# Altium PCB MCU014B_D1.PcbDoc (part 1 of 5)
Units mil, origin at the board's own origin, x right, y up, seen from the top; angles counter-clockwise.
Board outline 2300.04 x 4058 mil, 4 copper layers (TOP, GND, PWR, BOTTOM), stack 48.84 mil thick; 371 components, 238 nets, 1148 pads, 688 vias.
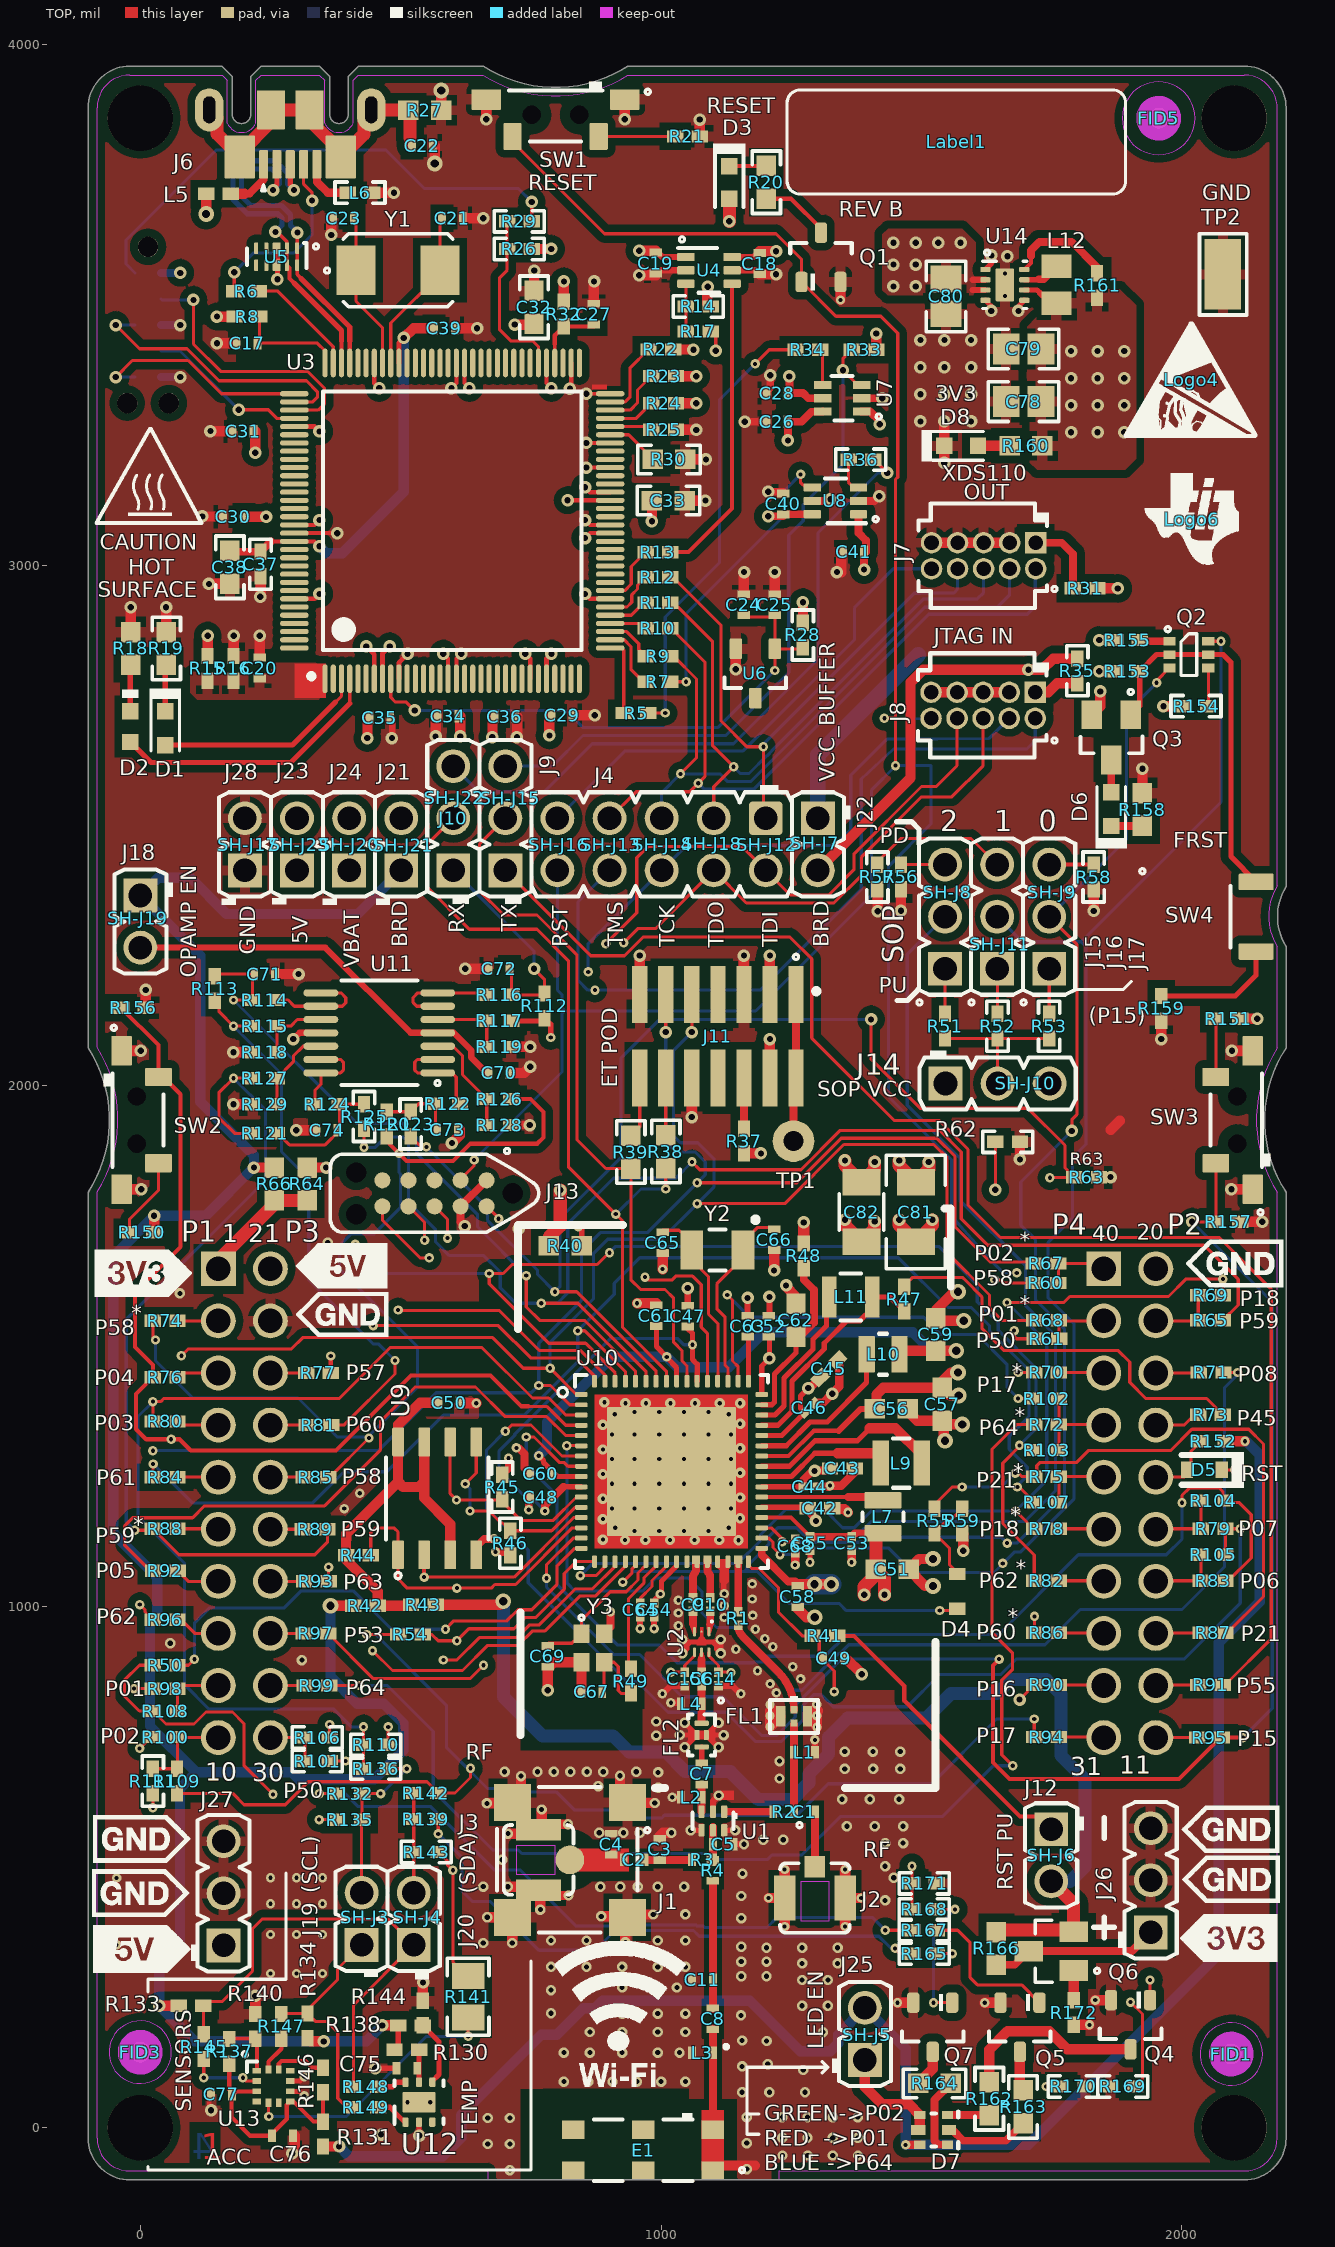
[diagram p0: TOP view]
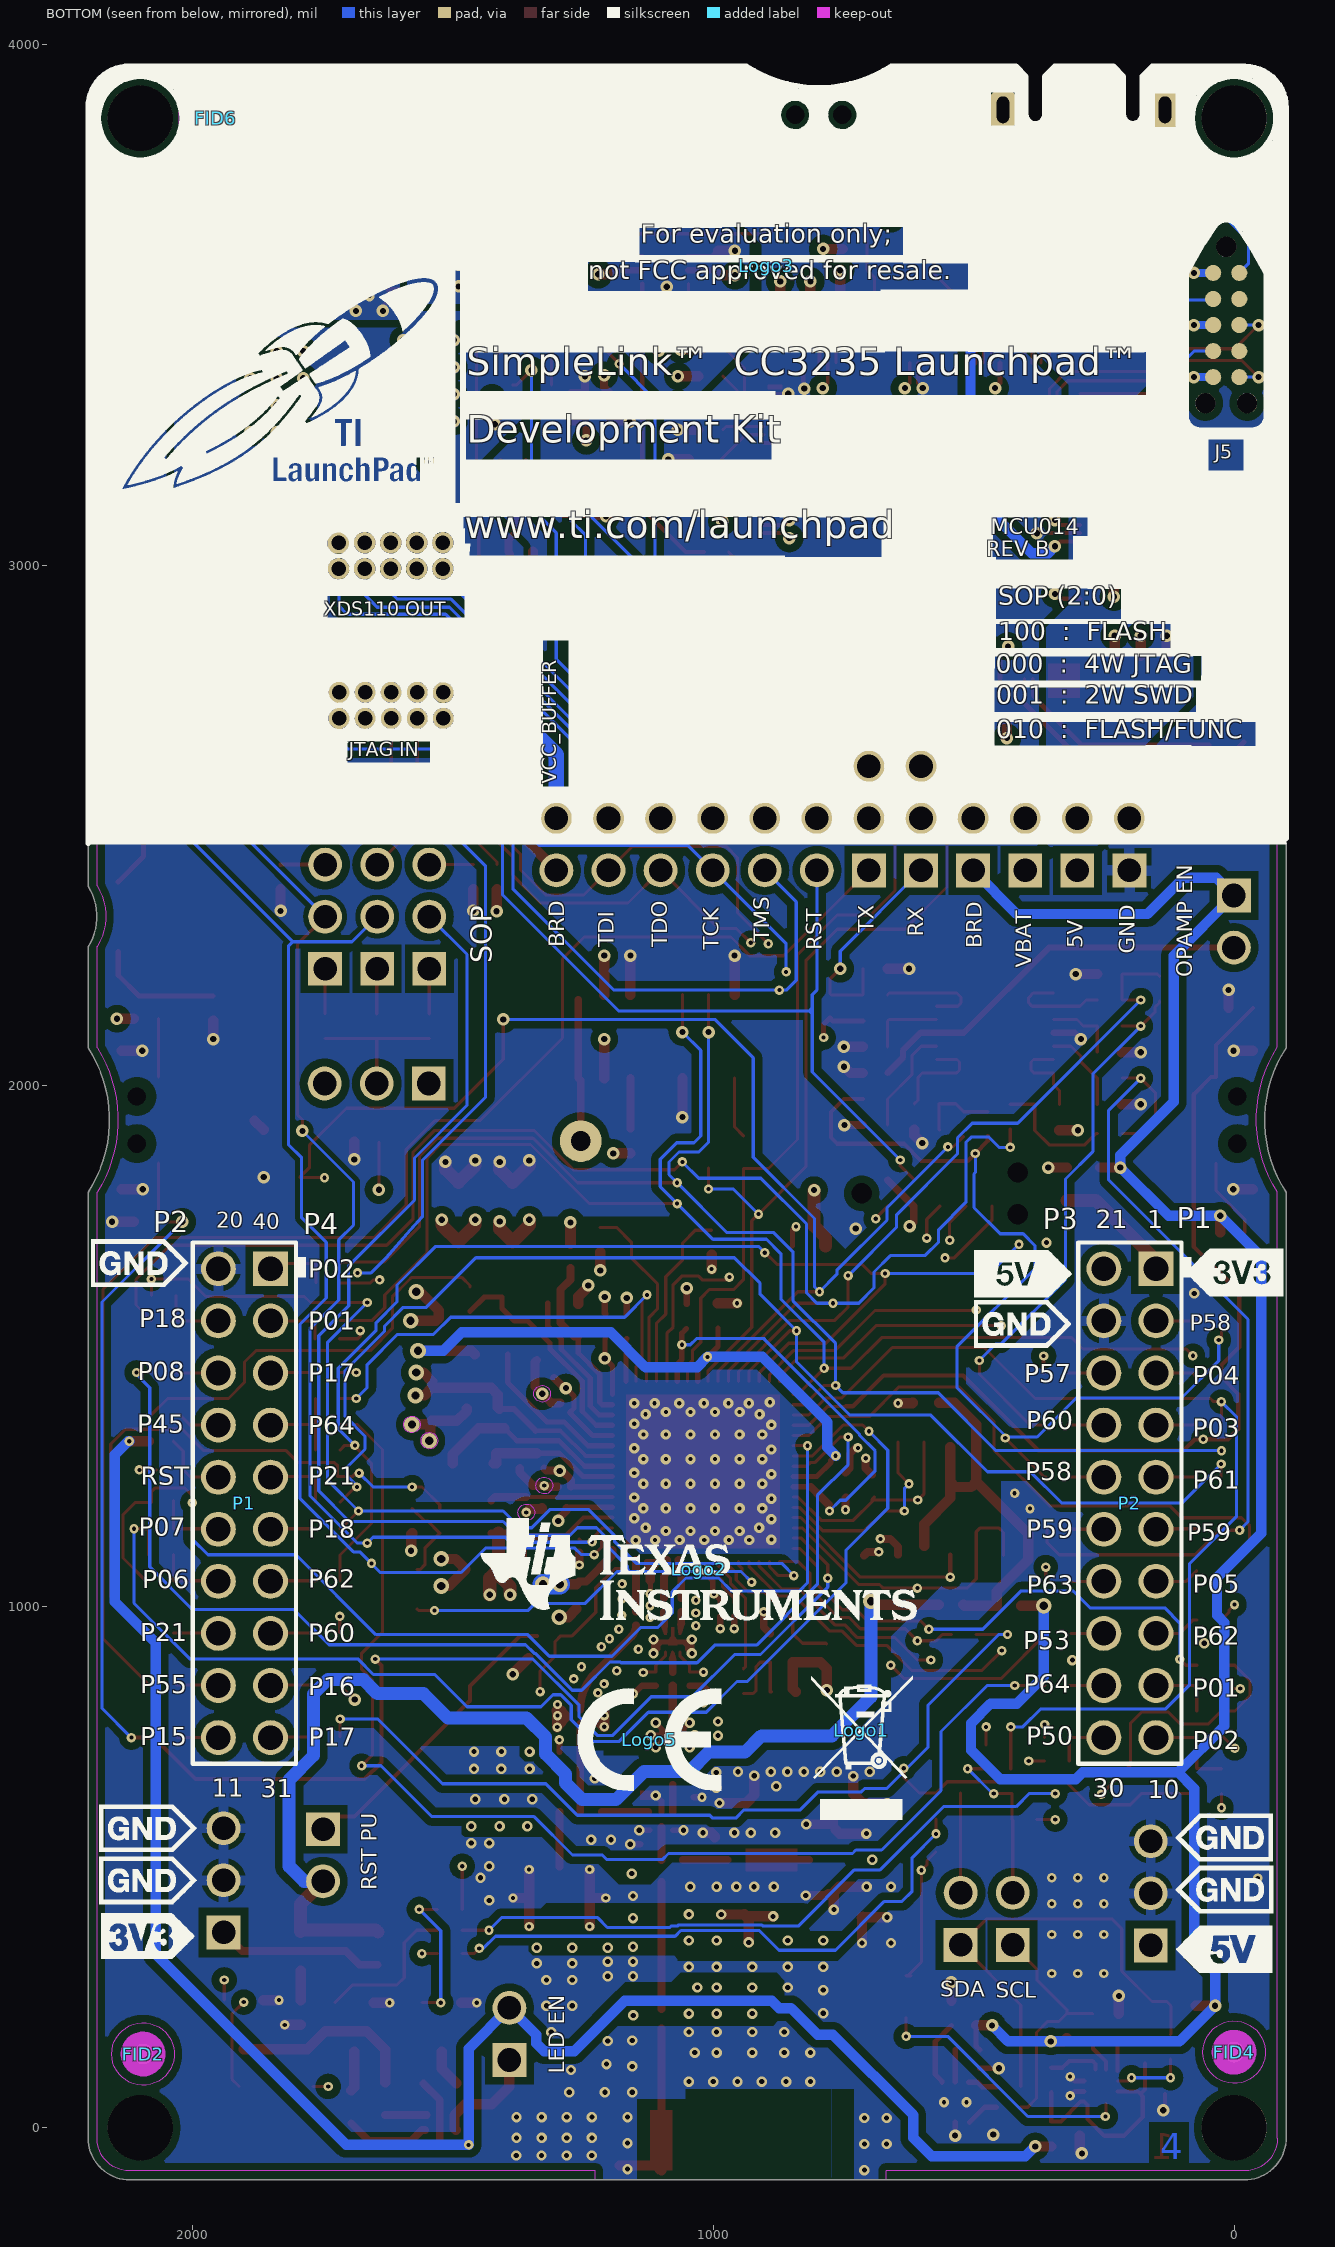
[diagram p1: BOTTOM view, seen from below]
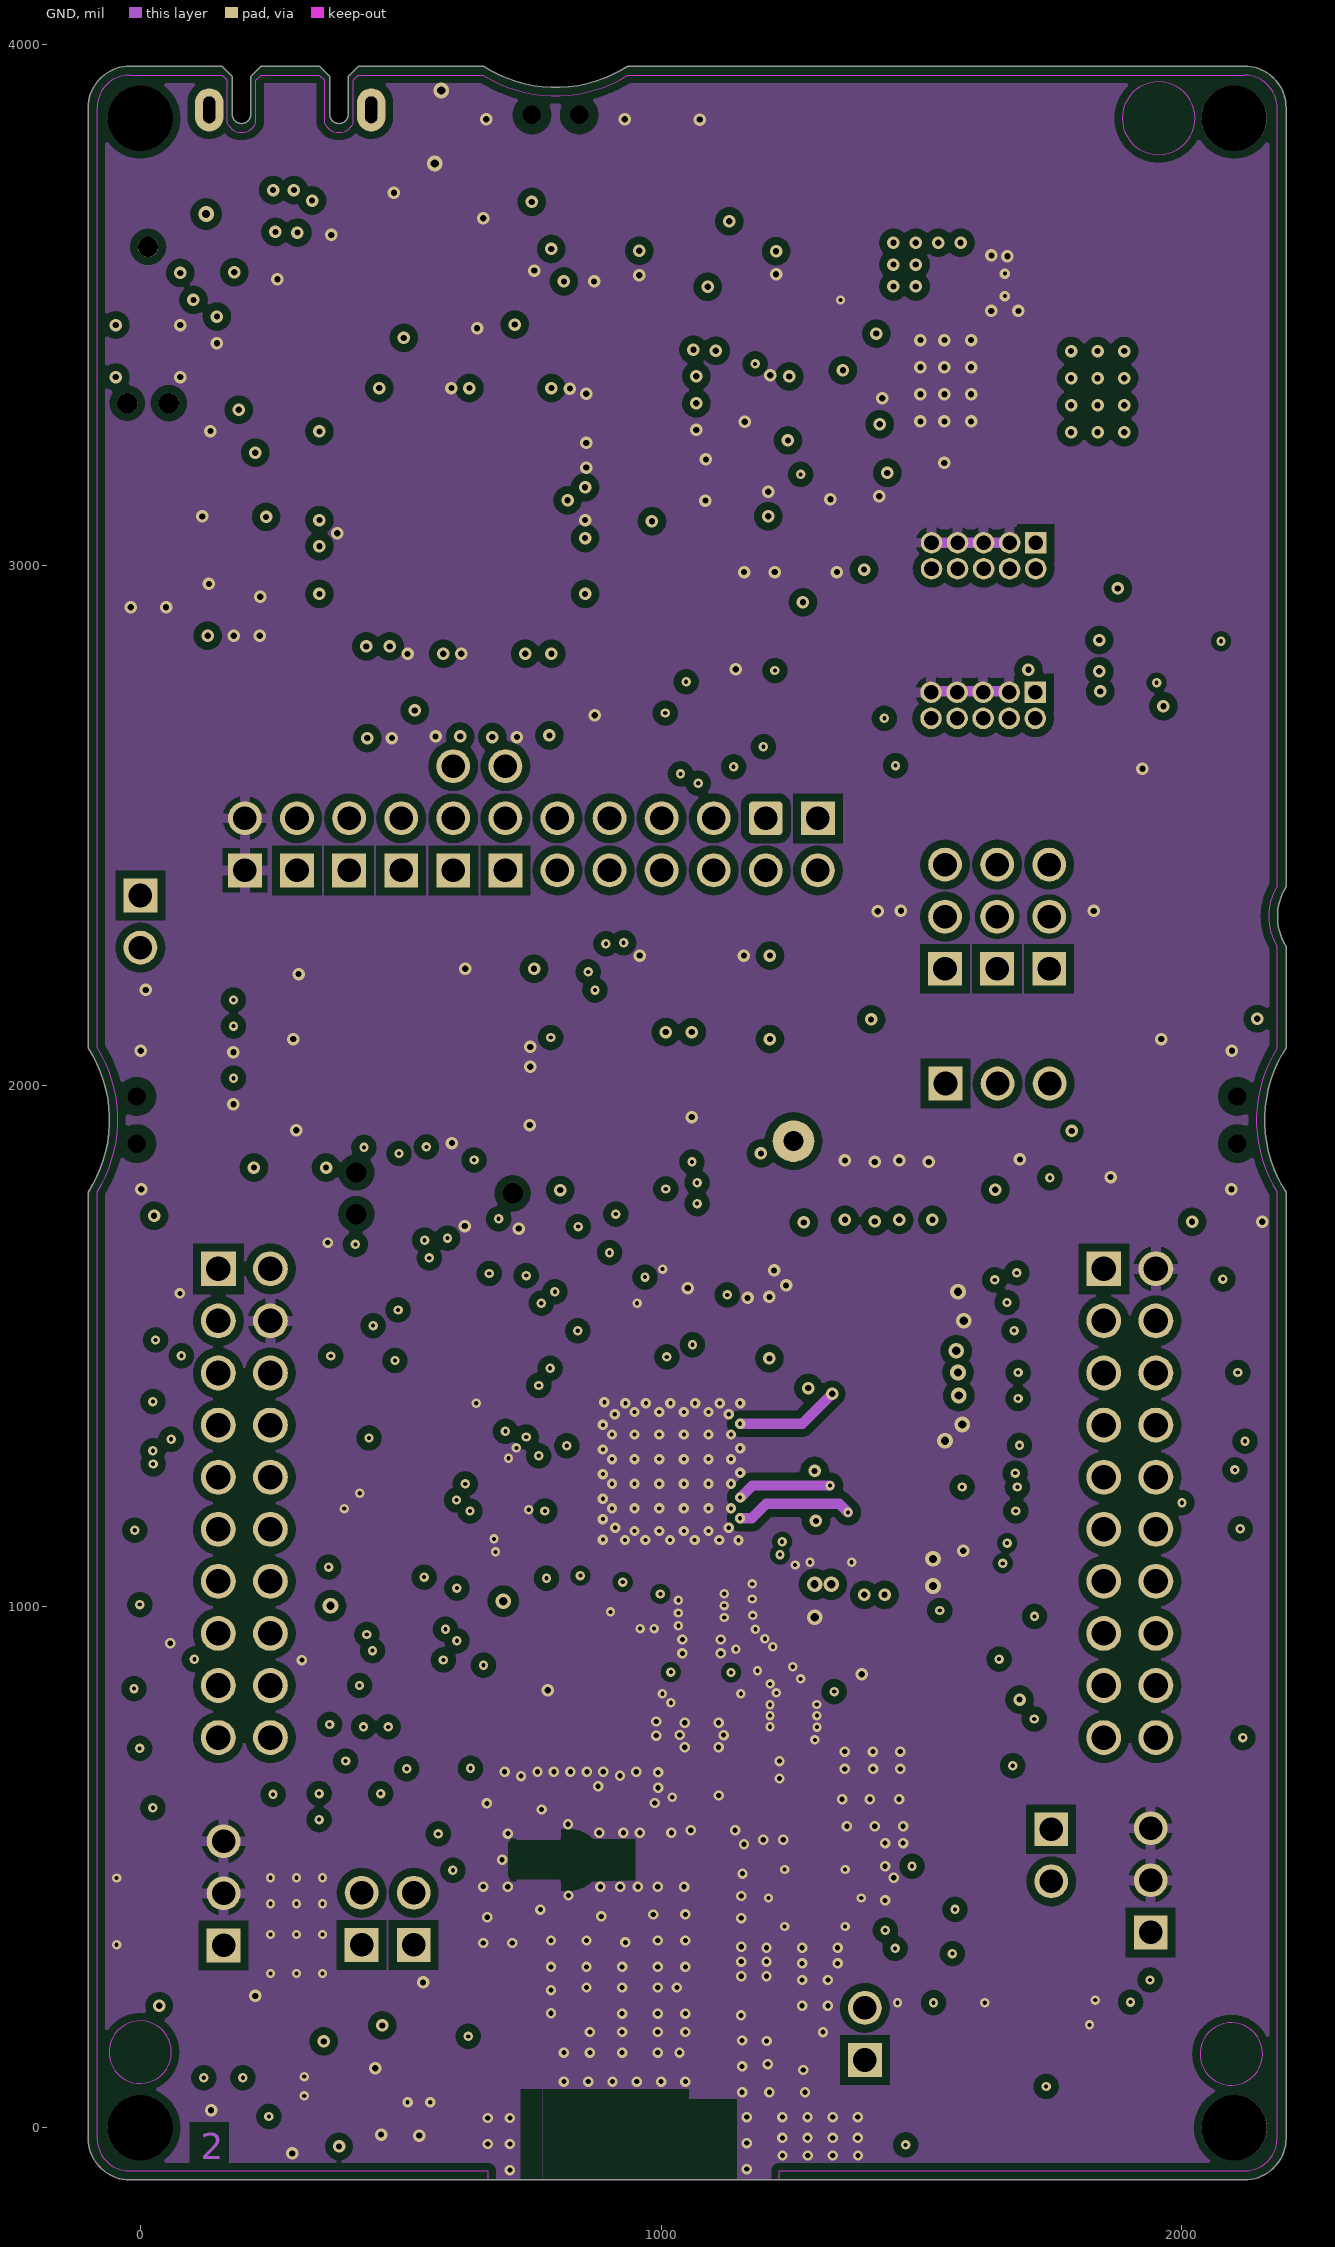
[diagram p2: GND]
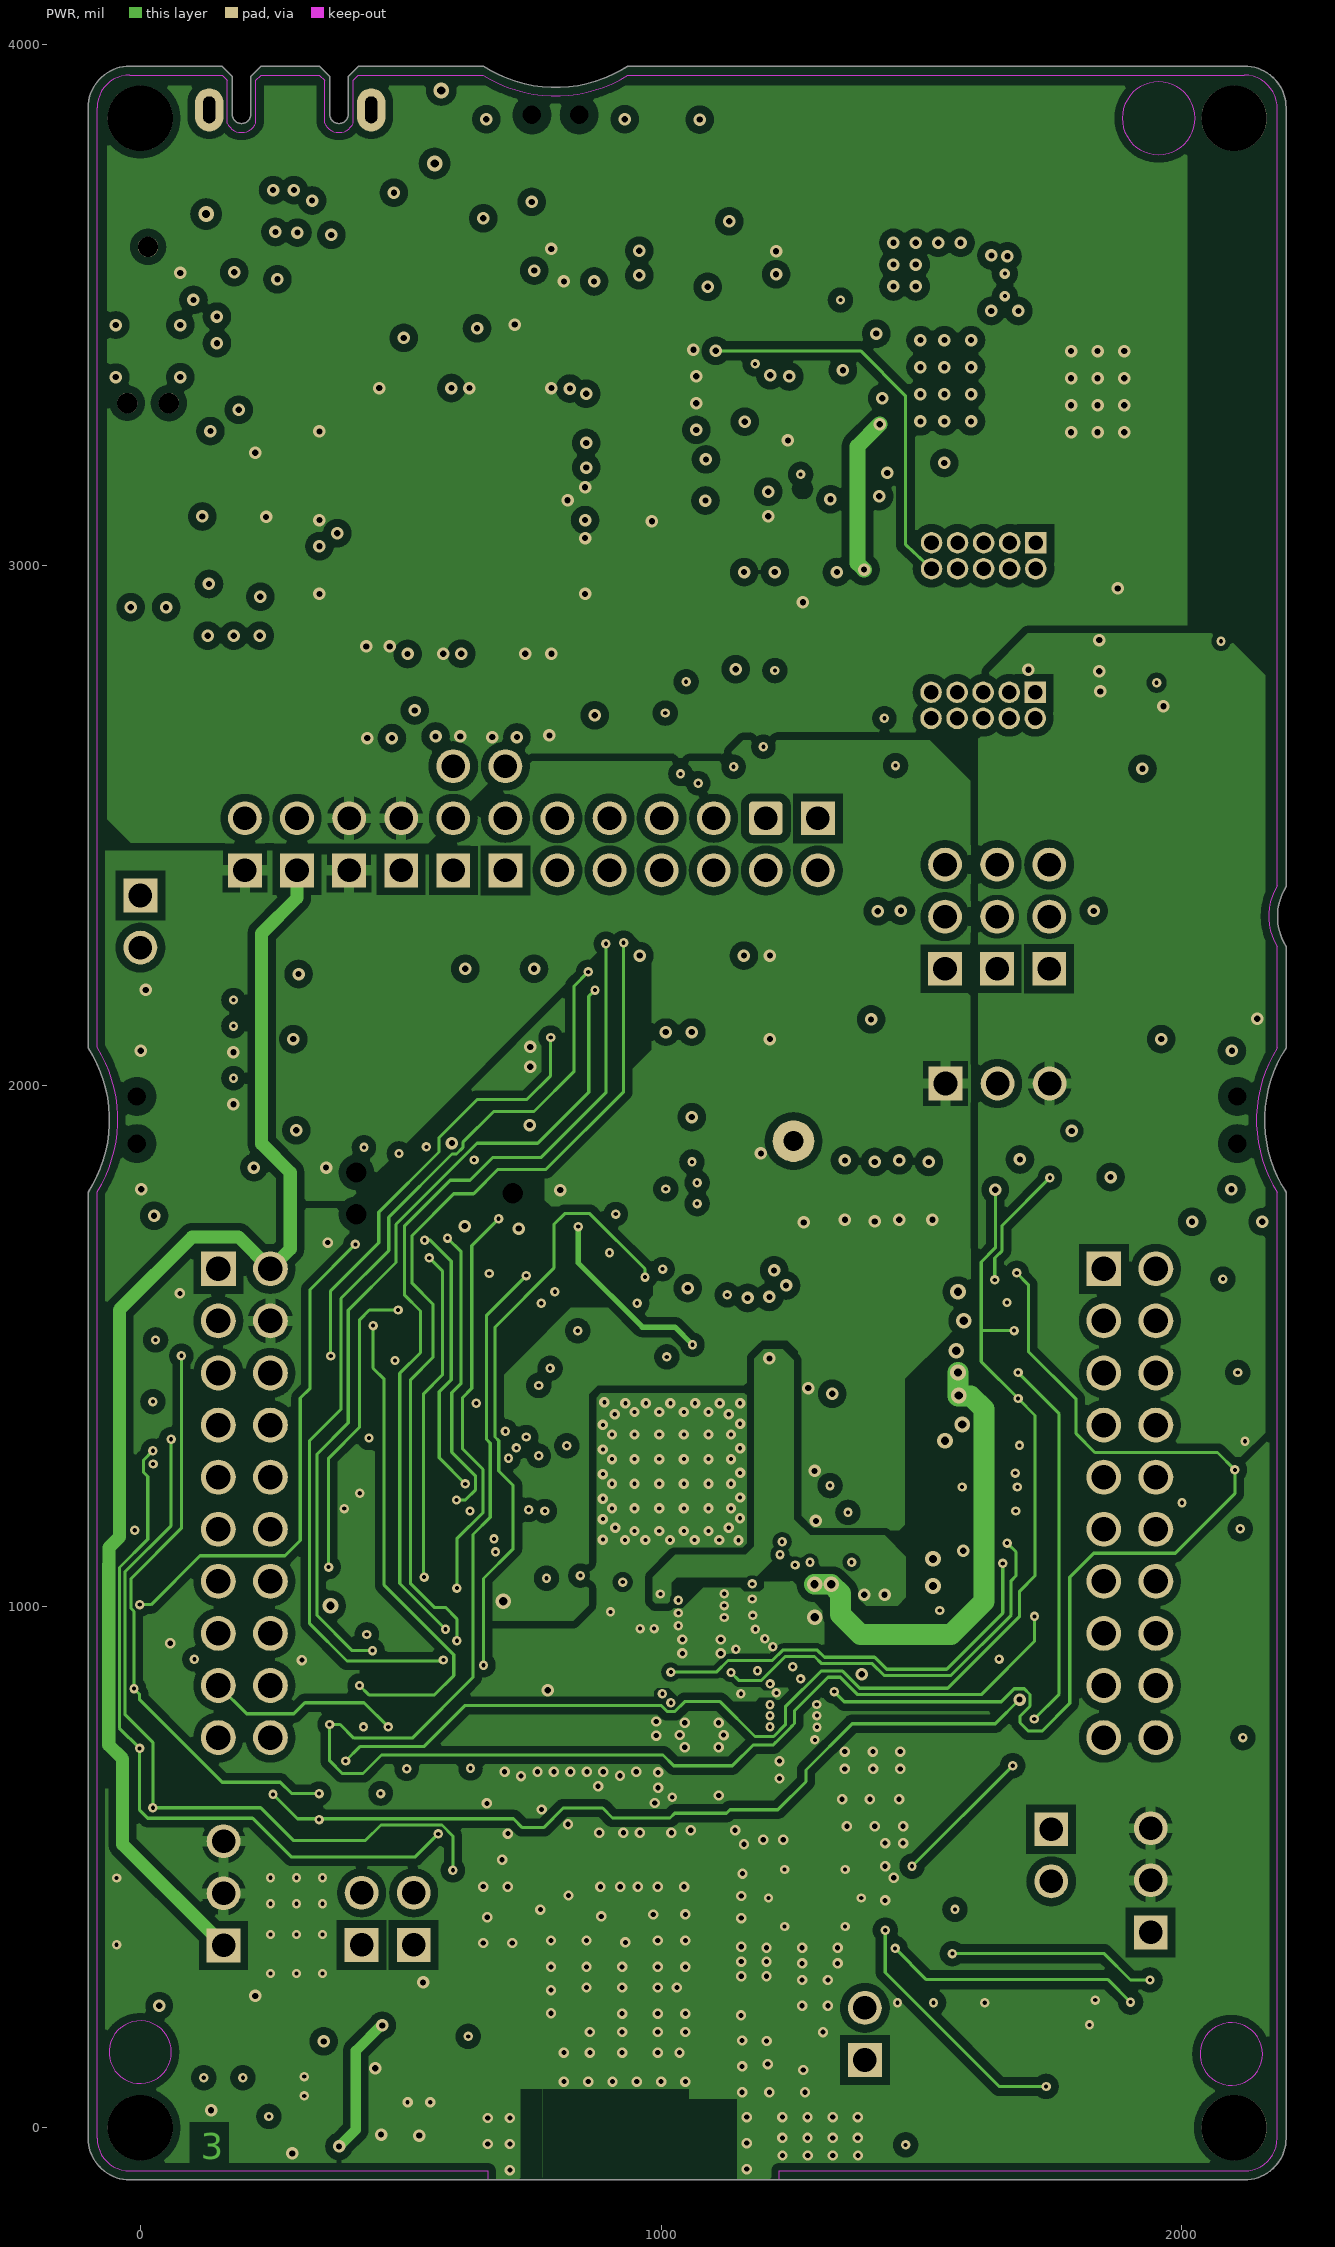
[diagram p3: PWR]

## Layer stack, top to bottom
Top Solder: solder mask 0.8, Solder Resist, Dk 4.1
TOP: signal copper 1.69
Dielectric1: core 9.3, FR-4 High Tg, Dk 3.9
GND: signal copper 1.42
Dielectric2: prepreg 24.02, FR-4 High Tg, Dk 4.24
PWR: signal copper 1.42
Dielectric3: core 9.3, FR-4 High Tg, Dk 3.9
BOTTOM: signal copper 1.69
Bottom Solder: solder mask 0.8, Solder Resist, Dk 4.1

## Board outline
-100,-20 -100,1796 ccw(c-313.24,1934.59) -100,2073.19 -100,3878 cw(c-20,3878) -20,3958 157.09,3958 176.78,3938.31 176.78,3865.48 ccw(c194.5,3865.48) 212.21,3865.48 212.21,3938.31 231.9,3958 344.1,3958 363.79,3938.31 363.79,3865.48 ccw(c381.5,3865.48) 399.22,3865.48 399.22,3938.31 418.91,3958 658.79,3958 ccw(c797.38,4171.24) 935.97,3958 2120,3958 cw(c2120,3878) 2200,3878 2200.01,2382.86 ccw(c2291.39,2325.29) 2200.04,2267.68 2200,2073.19 ccw(c2413.24,1934.59) 2200,1796 2200,-20 cw(c2120,-20) 2120,-100 -20,-100 cw(c-20,-20)

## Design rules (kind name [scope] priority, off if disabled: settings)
AssemblyTestPointUsage [All] p1 off:
Clearance Clearance_CPWG [InNetClass('RF_CPWG') vs inpoly] p1: gap=10 ignorepadtopadclearanceinfootprint=FALSE
Clearance Clearance_witinRoom1 [WithinRoom('Room1') and isvia vs InPoly] p2: gap=6 ignorepadtopadclearanceinfootprint=FALSE except(0: Arc-Hole Track-Hole SMDPad-Hole THPad-Hole Via-Hole Fill-Hole Poly-Hole Region-Hole Text-Hole)
Clearance Clearance_Via [WithinRoom('RoomVia') and IsVia vs InPoly and InNet('GND')] p3: gap=10 ignorepadtopadclearanceinfootprint=FALSE except(0: Arc-Hole Track-Hole SMDPad-Hole THPad-Hole Via-Hole Fill-Hole Poly-Hole Region-Hole Text-Hole)
Clearance Clearance_SMAPad [Inpoly vs ispad and InComponent('J1')] p4: gap=31.39 ignorepadtopadclearanceinfootprint=FALSE except(0: Arc-Hole Track-Hole SMDPad-Hole THPad-Hole Via-Hole Fill-Hole Poly-Hole Region-Hole Text-Hole)
Clearance Clearance_J1&J3 [InComponent('J1') vs InComponent('J3')] p5: gap=0 ignorepadtopadclearanceinfootprint=FALSE
Clearance Clearance_U3 [InComponent('U3') vs InComponent('U3')] p6: gap=4.8 ignorepadtopadclearanceinfootprint=FALSE except(0: Arc-Hole Track-Hole SMDPad-Hole THPad-Hole Via-Hole Fill-Hole Poly-Hole Region-Hole Text-Hole)
Clearance Clearance_Room2 [WithinRoom('Room_2')] p7: gap=4 ignorepadtopadclearanceinfootprint=FALSE except(0: Arc-Hole Track-Hole SMDPad-Hole THPad-Hole Via-Hole Fill-Hole Poly-Hole Region-Hole Text-Hole)
Clearance Clearance_GPIO_26&27 [(InNet('P30_GPIO_27') OR InNet('P29_GPIO_26')) AND Isvia and WithinRoom('Room1') vs inpoly and (OnLayer('gnd') or OnLayer('pwr'))] p8: gap=6 ignorepadtopadclearanceinfootprint=FALSE except(0: Arc-Hole Track-Hole SMDPad-Hole THPad-Hole Via-Hole Fill-Hole Poly-Hole Region-Hole Text-Hole)
Clearance Clearance_NetC69_1 [InNet('NetC69_1') or InNet('NetC65_1') or InNet('SOP0') or InNet('SOP1') vs InPoly] p9: gap=10 ignorepadtopadclearanceinfootprint=FALSE except(0: Arc-Hole Track-Hole SMDPad-Hole THPad-Hole Via-Hole Fill-Hole Poly-Hole Region-Hole Text-Hole)
Clearance Clearance_MH [InPadClass('MH') vs InPoly] p10: gap=20 ignorepadtopadclearanceinfootprint=FALSE except(0: Arc-Hole Track-Hole SMDPad-Hole THPad-Hole Via-Hole Fill-Hole Poly-Hole Region-Hole Text-Hole)
Clearance Clearance_U14 [InComponent('U14') vs InComponent('U14')] p11: gap=4.8 ignorepadtopadclearanceinfootprint=FALSE except(0: Arc-Hole Track-Hole SMDPad-Hole THPad-Hole Via-Hole Fill-Hole Poly-Hole Region-Hole Text-Hole)
Clearance Clearance_10 [InNetClass('Impedance') vs Inpoly] p12: gap=30 ignorepadtopadclearanceinfootprint=FALSE except(0: Arc-Hole Track-Hole SMDPad-Hole THPad-Hole Via-Hole Fill-Hole Poly-Hole Region-Hole Text-Hole)
Clearance Clearance_Exposed [OnLayer('Keep-Out Layer') vs InComponentClass('Expose')] p13: gap=0 ignorepadtopadclearanceinfootprint=FALSE
Clearance Clearance_Antenna [InComponent('E1') and IsKeepOut vs InPoly] p14: gap=0 ignorepadtopadclearanceinfootprint=FALSE
Clearance Clearance_8 [InPadClass('u1') vs istrack] p15: gap=5.9 ignorepadtopadclearanceinfootprint=FALSE except(0: Arc-Hole Track-Hole SMDPad-Hole THPad-Hole Via-Hole Fill-Hole Poly-Hole Region-Hole Text-Hole)
Clearance Clearance_7 [InPadClass('u1') vs InPadClass('u1')] p16: gap=5.9 ignorepadtopadclearanceinfootprint=FALSE except(0: Arc-Hole Track-Hole SMDPad-Hole THPad-Hole Via-Hole Fill-Hole Poly-Hole Region-Hole Text-Hole)
Clearance Clearance_6 [InNet('NetC49_2') vs InPolygon] p17: gap=15 ignorepadtopadclearanceinfootprint=FALSE except(0: Arc-Hole Track-Hole SMDPad-Hole THPad-Hole Via-Hole Fill-Hole Poly-Hole Region-Hole Text-Hole)
Clearance Clearance_5 [InNet('NetC49_1') vs InPolygon] p18: gap=15 ignorepadtopadclearanceinfootprint=FALSE except(0: Arc-Hole Track-Hole SMDPad-Hole THPad-Hole Via-Hole Fill-Hole Poly-Hole Region-Hole Text-Hole)
Clearance Clearance_4 [InNet('NetFL1_3') vs InPolygon] p19: gap=15 ignorepadtopadclearanceinfootprint=FALSE except(0: Arc-Hole Track-Hole SMDPad-Hole THPad-Hole Via-Hole Fill-Hole Poly-Hole Region-Hole Text-Hole)
Clearance Clearance_3 [InNet('NetFL1_1') vs InPolygon] p20: gap=15 ignorepadtopadclearanceinfootprint=FALSE except(0: Arc-Hole Track-Hole SMDPad-Hole THPad-Hole Via-Hole Fill-Hole Poly-Hole Region-Hole Text-Hole)
Clearance Clearance_2 [InNet('NetJ24_2') vs InPolygon] p21: gap=15 ignorepadtopadclearanceinfootprint=FALSE except(0: Arc-Hole Track-Hole SMDPad-Hole THPad-Hole Via-Hole Fill-Hole Poly-Hole Region-Hole Text-Hole)
Clearance Clearance_PAD [IsPad vs IsVia] p22: gap=8 ignorepadtopadclearanceinfootprint=FALSE except(0: Arc-Hole Track-Hole SMDPad-Hole THPad-Hole Via-Hole Fill-Hole Poly-Hole Region-Hole Text-Hole)
Clearance Clearance_net1 [InNet('NetJ24_1') vs InPolygon] p23: gap=15 ignorepadtopadclearanceinfootprint=FALSE except(0: Arc-Hole Track-Hole SMDPad-Hole THPad-Hole Via-Hole Fill-Hole Poly-Hole Region-Hole Text-Hole)
Clearance Clearance_Pad_class [InPadClass('Pad To Pad') vs IsPad] p24: gap=7.7 ignorepadtopadclearanceinfootprint=FALSE except(0: Arc-Hole Track-Hole SMDPad-Hole THPad-Hole Via-Hole Fill-Hole Poly-Hole Region-Hole Text-Hole)
Clearance Clearance_Pad_class_1 [InComponent('FID1') or              InComponent('FID2') or  InComponent('FID3') or        InComponent('FID4') or              InComponent('FID5') or  InComponent('FID6') vs IsKeepOut] p25: gap=0 ignorepadtopadclearanceinfootprint=FALSE except(7.7: Arc-Arc Arc-Track Track-Track)
Clearance Clearance_Poly_Poly [InPolygon vs InPolygon] p26: gap=15 ignorepadtopadclearanceinfootprint=FALSE except(0: Arc-Hole Track-Hole SMDPad-Hole THPad-Hole Via-Hole Fill-Hole Poly-Hole Region-Hole Text-Hole)
Clearance Clearance_VDD_ANA [inpoly and innet('VDD_ANA') and OnLayer('PWR') vs IsVia] p27: gap=8 ignorepadtopadclearanceinfootprint=FALSE except(0: Arc-Hole Track-Hole SMDPad-Hole THPad-Hole Via-Hole Fill-Hole Poly-Hole Region-Hole Text-Hole)
Clearance Clearance_Poly_Others [InPolygon] p28: gap=15 ignorepadtopadclearanceinfootprint=FALSE except(0: Arc-Hole Track-Hole SMDPad-Hole THPad-Hole Via-Hole Fill-Hole Poly-Hole Region-Hole Text-Hole)
Clearance Clearance_1 [iskeepout] p29: gap=1 ignorepadtopadclearanceinfootprint=FALSE except(0: Arc-Hole Track-Hole SMDPad-Hole THPad-Hole Via-Hole Fill-Hole Poly-Hole Region-Hole Text-Hole)
Clearance Clearance_9 [InNet('XDSET_DP') vs InNet('XDSET_DM')] p30: gap=6 ignorepadtopadclearanceinfootprint=FALSE except(0: Arc-Hole Track-Hole SMDPad-Hole THPad-Hole Via-Hole Fill-Hole Poly-Hole Region-Hole Text-Hole)
Clearance [All] p31: gap=3.5 ignorepadtopadclearanceinfootprint=FALSE
ComponentClearance ComponentClearance_Shunt [HasFootprint('Wurth_60900213421')] p1: gap=0 collisioncheckmode=3 verticalgap=0 showdistances=FALSE
ComponentClearance ComponentClearance_Overlap [InComponentClass('Overlap') vs InComponentClass('Overlap')] p2: gap=0 collisioncheckmode=3 verticalgap=0 showdistances=FALSE
ComponentClearance ComponentClearance_SMA&UFL [InComponent('J1') vs InComponent('J3')] p3: gap=0 collisioncheckmode=3 verticalgap=0 showdistances=FALSE
ComponentClearance ComponentClearance_C7_R168 [InComponent('C7') vs InComponent('R168')] p4: gap=0 collisioncheckmode=3 verticalgap=0 showdistances=FALSE
ComponentClearance ComponentClearance_R3_R170 [InComponent('R3') vs InComponent('R4')] p5: gap=0 collisioncheckmode=3 verticalgap=0 showdistances=FALSE
ComponentClearance [All] p6: gap=3.5 collisioncheckmode=3 verticalgap=3.5 showdistances=FALSE
DiffPairsRouting [All] p1: maxlimit=10 minlimit=6 mostfreqgap=6 toplayer_minwidth=8 toplayer_maxwidth=15 toplayer_prefwidth=10 midlayer1_minwidth=8 midlayer1_maxwidth=15 midlayer1_prefwidth=10 midlayer2_minwidth=8 midlayer2_maxwidth=15 midlayer2_prefwidth=10 bottomlayer_minwidth=8 bottomlayer_maxwidth=15 bottomlayer_prefwidth=10 maxuncoupledlength=500
FabricationTestPointUsage [All] p1 off: valid=0 allowmultiple=FALSE
FabricationTestpoint [All] p1 off: side=3 testpointundercomponent=TRUE minsize=40 maxsize=100 preferedsize=60 minholesize=0 maxholesize=40 preferedholesize=32 testpointgrid=1 allowsidetop=TRUE allowsidebottom=TRUE usegrid=TRUE gridtolerance=0.01
Height [All] p1: minheight=0 maxheight=1300 prefheight=500
HoleSize [All] p1: absolutevalues=TRUE maxlimit=125 minlimit=5.9 maxpercent=80.000 minpercent=20.000
MinimumAnnularRing [All] p1: minimumring=4
MinimumSolderMaskSliver [All] p1: minsoldermaskwidth=3
PlaneClearance [All] p1: clearance=8
PlaneConnect PlaneConnect_1 [All] p1: planeconnectstyle=Direct reliefexpansion=20 reliefentries=4 reliefconductorwidth=10 reliefairgap=10
PolygonConnect PolygonConnect_1 [isvia] p1: connectstyle=Direct reliefconductorwidth=10 reliefentries=4 polygonreliefangle="90 Angle" airgapwidth=10
PolygonConnect [InComponentClass('CC3200Gen3_AntennaRFSection') or InPadClass('direct connect')] p2: connectstyle=Direct reliefconductorwidth=10 reliefentries=4 polygonreliefangle="90 Angle" airgapwidth=10
PolygonConnect PolygonConnect_SMD [All] p3: connectstyle=Relief reliefconductorwidth=20 reliefentries=4 polygonreliefangle="90 Angle" airgapwidth=10
RoomDefinition RoomVia [InComponentClass('Components Class 1')] p1: confinementstyle=ConfineIn formatcopy=TRUE lockcomponents=FALSE outline 834.49,1100.65 1180.32,1100.65 1180.32,856.05 834.49,856.05
RoutingVias [All] p1: holewidth=8 width=18 viastyle="Through Hole" minholewidth=7.8 minwidth=12 maxholewidth=28 maxwidth=50
ShortCircuit ShortCircuit_1 [InPadClass('FID')] p1: allowed=TRUE
ShortCircuit [All] p2: allowed=FALSE
SilkToSilkClearance SilkToSilkClearance_Fill [IsObjectKind('Fill')] p1: silktosilkclearance=0
SilkToSilkClearance SilkToSilkClearance_pb-logo [(HasFootprint('Pb-Free_Overlay_Medium') OR HasFootprint('Pb-Free_Overlay_Small')) vs (HasFootprint('Pb-Free_Overlay_Medium') OR HasFootprint('Pb-Free_Overlay_Small'))] p2: silktosilkclearance=0
SilkToSilkClearance SilkToSilkClearance_invert [IsObjectKind('Text')] p3: silktosilkclearance=0
SilkToSilkClearance [All] p4: silktosilkclearance=3
SilkToSolderMaskClearance SilkToSolderMaskClearance_4 [InComponent('P2')] p1: minsilkscreentomaskgap=0 clearancetoexposedcopper=TRUE
SilkToSolderMaskClearance SilkToSolderMaskClearance_3 [OnLayer('Bottom Silkscreen')] p2: minsilkscreentomaskgap=0 clearancetoexposedcopper=TRUE
SilkToSolderMaskClearance SilkToSolderMaskClearance_1 [InComponent('J1') or InComponent('J3')] p3: minsilkscreentomaskgap=1 clearancetoexposedcopper=TRUE
SilkToSolderMaskClearance SilkToSolderMaskClearance_2 [InComponent('J7') or InComponent('J11') or  InComponent('J9') or InComponent('J8') or  InComponent('J24') or InComponent('J26') or InComponent('J25') or InComponent('J23') or InComponent('FID5') or InComponent('FID6')  or InComponent('J6') or InComponent('J4') or  InComponent('J29')] p4: minsilkscreentomaskgap=0 clearancetoexposedcopper=TRUE
SilkToSolderMaskClearance [IsPad] p5: minsilkscreentomaskgap=3 clearancetoexposedcopper=FALSE
SilkToSolderMaskClearance SilkscreenOverComponentPads [IsPad] p6: minsilkscreentomaskgap=3 clearancetoexposedcopper=TRUE
SolderMaskExpansion SolderMaskExpansion_PTH [InPadClass('PTH')] p1: expansion=2.5
SolderMaskExpansion SolderMaskExpansion_MH [InPadClass('MH')] p2: expansion=5
SolderMaskExpansion SolderMaskExpansion_1 [InPadClass('MAsk')] p3: expansion=0.9
SolderMaskExpansion [All] p4: expansion=0
Width [All] p1: maxlimit=100 minlimit=5 preferedwidth=10
17 further rules are at their usual default settings.

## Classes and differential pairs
component class "New Class": C47 C55 C68 L4
pad class MH: SW1- SW2- SW3- SW4-MH1 SW4-MH2
pad class MAsk: U1-1 U1-2 U1-3 U1-4 U1-5 U1-6 U1-7 U1-8 U1-9 U1-10 U1-11 U1-12 U1-13 U1-14 U1-15 U1-16 U1-17 U1-18 U1-19 U1-20 U1-21 U1-22 U1-23 U1-24 U1-25 U1-26 U1-27 U1-28 U1-29 U1-30 U1-31 U1-32 U1-33 U1-34 U1-35 U1-36 U1-37 U1-38 U1-39 U1-40 U1-41 U1-42 U1-43 U1-44 U1-45 U1-46 U1-47 U1-48 U1-49 U1-50 U1-51 U1-52 U1-53 U1-54 U1-55 U1-56 U1-57 U1-58 U1-59 U1-60 U1-61 U1-62 U1-63 U1-64 U1-65 U1-66 U1-67 U1-68 U1-69 U1-70 U1-71 U1-72 U1-73 U1-74 U1-75 U1-76 U1-77 U1-78 U1-79 U1-80 U1-81 U1-82 U1-83 U1-84 U1-85 U1-86 U1-87 U1-88 U1-89 U1-90 U1-91 U1-92 U1-93 U1-94 U1-95 U1-96 U1-97 U1-98 U1-99 U1-100 U1-101 U1-102 U1-103 U1-104 U1-105 U1-106 U1-107 U1-108 U1-109 U1-110 U1-111 U1-112 U1-113 U1-114 U1-115 U1-116 U1-117 U1-118 U1-119 U1-120 U1-121 U1-122 U1-123 U1-124 U1-125 U1-126 U1-127 U1-128
pad class "direct connect": C3-2 C4-2 C5-2 C11-2 C14-2 C15-2 FL1-2 FL1-4 L1-2 L2-2 L3-2 L4-1 U1-2 U1-4 U1-6
component class FiducialMark: FID1 FID2 FID3 FID4 FID5 FID6
component class MCU014B_D1_EngineArea: C42 C43 C44 C45 C46 C47 C48 C49 C50 C51 C52 C53 C54 C55 C56 C57 C58 C59 C60 C61 C62 C63 C64 C65 C66 C67 C68 C69 D4 J12 J13 J14 J15 J16 J17 L7 L9 L10 L11 R40 R41 R42 R43 R44 R45 R46 R47 R48 R49 R50 R51 R52 R53 R54 R55 R56 R57 R58 R59 U9 U10 Y2 Y3
component class MCU014B_D1_HostInterface_ADC: C70 C71 C72 C73 C74 J18 P1 P2 R60 R61 R62 R63 R64 R65 R66 R67 R68 R69 R70 R71 R72 R73 R74 R75 R76 R77 R78 R79 R80 R81 R82 R83 R84 R85 R86 R87 R88 R89 R90 R91 R92 R93 R94 R95 R96 R97 R98 R99 R100 R101 R102 R103 R104 R105 R106 R107 R108 R109 R110 R111 R112 R113 R114 R115 R116 R117 R118 R119 R120 R121 R122 R123 R124 R125 R126 R127 R128 R129 U11
component class MCU014B_D1_EmulationCircuit: C17 C18 C19 C20 C21 C22 C23 C24 C25 C26 C27 C28 C29 C30 C31 C32 C33 C34 C35 C36 C37 C38 C39 C40 C41 D1 D2 D3 J4 J5 J6 J7 J8 J9 J10 J11 L5 L6 Q1 R5 R6 R7 R8 R9 R10 R11 R12 R13 R14 R15 R16 R17 R18 R19 R20 R21 R22 R23 R24 R25 R26 R27 R28 R29 R30 R31 R32 R33 R34 R35 R36 R37 R38 R39 SW1 TP1 U3 U4 U5 U6 U7 U8 Y1
component class MCU014B_D1_PowerLedsSwitchSensors: C75 C76 C77 C78 C79 C80 C81 C82 D5 D6 D7 D8 J19 J20 J21 J22 J23 J24 J25 J26 J27 J28 L12 Q2 Q3 Q4 Q5 Q6 Q7 R130 R131 R132 R133 R134 R135 R136 R137 R138 R139 R140 R141 R142 R143 R144 R145 R146 R147 R148 R149 R150 R151 R152 R153 R154 R155 R156 R157 R158 R159 R160 R161 R162 R163 R164 R165 R166 R167 R168 R169 R170 R171 R172 SW2 SW3 SW4 TP2 U12 U13 U14
component class AssemblyNote: ZZ1 ZZ2 ZZ3 ZZ4
component class MCU014B_D1_EVM_Hardware: FID1 FID2 FID3 FID4 FID5 FID6 Label1 Logo1 Logo2 Logo3 Logo4 Logo5 Logo6 SH-J3 SH-J4 SH-J5 SH-J6 SH-J7 SH-J8 SH-J9 SH-J10 SH-J11 SH-J12 SH-J13 SH-J14 SH-J15 SH-J16 SH-J17 SH-J18 SH-J19 SH-J20 SH-J21 SH-J22 SH-J23 ZZ1 ZZ2 ZZ3 ZZ4
component class Header: J4 J9 J10 J11 J12 J14 J15 J16 J17 J18 J19 J20 J21 J22 J23 J24 J25 J26 J27 J28
component class Label: Label1
component class Logo: Logo2 Logo6
pad class u1: U1-1 U1-2 U1-3 U1-4 U1-5 U1-6 U1-7 U1-8 U1-9 U1-10 U1-11 U1-12 U1-13 U1-14 U1-15 U1-16 U1-17 U1-18 U1-19 U1-20 U1-21 U1-22 U1-23 U1-24 U1-25 U1-26 U1-27 U1-28 U1-29 U1-30 U1-31 U1-32 U1-33 U1-34 U1-35 U1-36 U1-37 U1-38 U1-39 U1-40 U1-41 U1-42 U1-43 U1-44 U1-45 U1-46 U1-47 U1-48 U1-49 U1-50 U1-51 U1-52 U1-53 U1-54 U1-55 U1-56 U1-57 U1-58 U1-59 U1-60 U1-61 U1-62 U1-63 U1-64 U1-65 U1-66 U1-67 U1-68 U1-69 U1-70 U1-71 U1-72 U1-73 U1-74 U1-75 U1-76 U1-77 U1-78 U1-79 U1-80 U1-81 U1-82 U1-83 U1-84 U1-85 U1-86 U1-87 U1-88 U1-89 U1-90 U1-91 U1-92 U1-93 U1-94 U1-95 U1-96 U1-97 U1-98 U1-99 U1-100 U1-101 U1-102 U1-103 U1-104 U1-105 U1-106 U1-107 U1-108 U1-109 U1-110 U1-111 U1-112 U1-113 U1-114 U1-115 U1-116 U1-117 U1-118 U1-119 U1-120 U1-121 U1-122 U1-123 U1-124 U1-125 U1-126 U1-127 U1-128
component class MCU014B_D1_AntennaRFSection: C1 C2 C3 C4 C5 C6 C7 C8 C9 C10 C11 C14 C15 E1 FL1 FL2 J1 J2 J3 L1 L2 L3 L4 R1 R2 R3 R4 U1 U2
pad class PTH: J4-1 J4-2 J4-3 J4-4 J4-5 J4-6 J4-7 J4-8 J4-9 J4-10 J6-7 J6-10 J7-1 J7-2 J7-3 J7-4 J7-5 J7-6 J7-7 J7-8 J7-9 J7-10 J8-1 J8-2 J8-3 J8-4 J8-5 J8-6 J8-7 J8-8 J8-9 J8-10 J9-1 J9-2 J9-3 J10-1 J10-2 J10-3 J12-1 J12-2 J14-1 J14-2 J14-3 J15-1 J15-2 J15-3 J16-1 J16-2 J16-3 J17-1 J17-2 J17-3 J18-1 J18-2 J19-1 J19-2 J20-1 J20-2 J21-1 J21-2 J22-1 J22-2 J23-1 J23-2 J24-1 J24-2 J25-1 J25-2 J26-1 J26-2 J26-3 J27-1 J27-2 J27-3 J28-1 J28-2 P1-1 P1-2 P1-3 P1-4 P1-5 P1-6 P1-7 P1-8 P1-9 P1-10 P1-11 P1-12 P1-13 P1-14 P1-15 P1-16 P1-17 P1-18 P1-19 P1-20 P2-1 P2-2 P2-3 P2-4 P2-5 P2-6 P2-7 P2-8 P2-9 P2-10 P2-11 P2-12 P2-13 P2-14 P2-15 P2-16 P2-17 P2-18 P2-19 P2-20 TP1-1
component class Overlap: C1 C2 C5 J4 J9 J10 J15 J16 J17 J19 J20 J21 J22 J23 J24 J28 R2 R4 R138 R144
net class RF_CPWG: A_RX A_TX NetC1_1 NetC1_2 NetC2_1 NetC2_2 NetC5_1 NetC6_2 NetC7_2 NetC8_1 NetC9_1 NetC10_1 NetFL1_1 NetR2_1 RF_BG

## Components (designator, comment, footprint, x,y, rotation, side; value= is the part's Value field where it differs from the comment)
C1 "CMP-0006408-2" 0402S 1275.31,606.65 r0 top locked value=10pF
C2 "0402N8R2C500CT" 0402S 948.26,514.21 r180 top value=8.2pF
C3 "GJM1555C1HR50BB01J" 0402S 997,534.21 r90 top value=0.5pF
C4 "GJM1555C1HR50BB01J" 0402S 904.51,544.46 r90 top value=0.5pF
C5 "GJM1555C1HR50BB01J" 0402S 1119.46,544.06 r0 top value=0.5pF
C6 "GRM0335C1H1R6BA01D" 0201_033 1077.81,861.71 r90 top value=1.6pF
C7 "GJM1555C1H1R9WB01D" 0402S 1077.81,679.21 r270 top value=1.9pF
C8 "GJM1555C1H2R2BB01D" 0402S 1099.46,209.21 r270 top locked value=2.2pF
C9 "GRM0335C1H4R7BA01D" 0201_033 1061.3,1004.21 r90 top value=4.7pF
C10 "GRM0335C1H4R7BA01D" 0201_033 1094.31,1004.21 r90 top value=4.7pF
C11 "CMP-0006426-2" 0402S 1079.46,284.21 r180 top value=1pF
C14 "CC0201JRNPO8BN101" 0201 1110.31,861.71 r270 top value=100pF
C15 "CC0201JRNPO8BN101" 0201 1045.31,861.71 r270 top value=100pF
C17 "CL05B104KO5NNNC" 0402S 205.21,3426.21 r180 top locked value=0.1uF
C18 "CL05B104KO5NNNC" 0402S 1189,3579 r270 top locked value=0.1uF
C19 "CL05B104KO5NNNC" 0402S 990,3580 r270 top locked value=0.1uF
C20 "0402B103K500CT" 0402S 229.38,2802.38 r90 top locked value=0.01uF
C21 "CL05C220JB5NNNC" 0402S 599.33,3665.91 r180 top locked value=22pF
C22 "0402B103K500CT" 0402S 541.5,3805 r0 top locked value=0.01uF
C23 "CL05C220JB5NNNC" 0402S 390.58,3665.83 r0 top locked value=22pF
C24 "0402B103K500CT" 0402S 1159,2924 r90 top locked value=0.01uF
C25 "CL05A105KA5NQNC" 0402S 1218,2924 r90 top locked value=1uF
C26 "CL05B104KO5NNNC" 0402S 1222.6,3275.41 r180 top locked value=0.1uF
C27 "CL05A105KA5NQNC" 0402S 871,3482 r90 top locked value=1uF
C28 "CL05B104KO5NNNC" 0402S 1222.6,3330.41 r180 top locked value=0.1uF
C29 "0402B103K500CT" 0402S 810,2712 r0 top locked value=0.01uF
C30 "0402B103K500CT" 0402S 179,3093 r180 top locked value=0.01uF
C31 "0402B103K500CT" 0402S 197.38,3257 r180 top locked value=0.01uF
C32 "CMP-0006758-5" 0603 756,3495 r90 top locked value=0.1uF
C33 "CMP-0006758-5" 0603 1014,3124 r0 top locked value=0.1uF
C34 "CL05A105KA5NQNC" 0402S 591,2710 r180 top locked value=1uF
C35 "0402B103K500CT" 0402S 460,2707 r0 top locked value=0.01uF
C36 "CL05A105KA5NQNC" 0402S 700,2709 r0 top locked value=1uF
C37 "CMP-0006275-2" 0402 231,3002 r270 top locked value=2.2uF
C38 "CMP-0006758-5" 0603 172,2996 r270 top locked value=0.1uF
C39 "CL05A105KA5NQNC" 0402S 584,3455 r0 top locked value=1uF
C40 "CL05B104KO5NNNC" 0402S 1234.6,3117.41 r90 top locked value=0.1uF
C41 "CL05B104KO5NNNC" 0402S 1369.6,3025.41 r180 top locked value=0.1uF
C42 "CMP-0064972-2" 0402 1305,1189.5 r0 top locked value=4.7uF
C43 "CMP-0064972-2" 0402 1347.91,1265.69 r0 top value=4.7uF
C44 "GJM0335C1ER60BB01D" 0201_033 1285.79,1230.47 r0 top value=0.6pF
C45 "CMP-0064972-2" 0402 1322.32,1456.71 r45 top value=4.7uF
C46 "GJM0335C1ER50BB01D" 0201_033 1284.87,1382.18 r45 top value=0.5pF
C47 "CL05B104KO5NNNC" 0402S 1051,1558 r90 top locked value=0.1uF
C48 "CL05B104KO5NNNC" 0402S 768.62,1210 r180 top locked value=0.1uF
C49 "0402B103K500CT" 0402S 1331.06,901.65 r0 top locked value=0.01uF
C50 "CL05B104KO5NNNC" 0402S 592.87,1392.1 r0 top locked value=0.1uF
C51 "CMP-0064953-4" 0603 1444,1072 r0 top locked value=10uF
C52 "CL05B104KO5NNNC" 0402S 1207,1539 r90 top locked value=0.1uF
C53 "GJM0335C1ER20BB01D" 0201_033 1365.68,1121.74 r270 top value=0.2pF
C54 "CL03A104KP3NNNC" 0201 986.58,994.26 r270 top value=0.1uF
C55 "GJM0335C1ER60BB01D" 0201_033 1285.88,1121.74 r270 top value=0.6pF
C56 "CMP-0064952-4" 0603 1442,1380 r0 top locked value=22uF
C57 "CMP-0064952-4" 0603 1540,1389 r270 top locked value=22uF
C58 "CL05A105MP5NNNC" 0402S 1262.64,1019.79 r270 top locked value=1uF
C59 "CMP-0064953-4" 0603 1527,1523 r90 top locked value=10uF
C60 "CL05B104KO5NNNC" 0402S 768.62,1256 r180 top locked value=0.1uF
C61 "CL05B104KO5NNNC" 0402S 991,1559 r90 top locked value=0.1uF
C62 "CMP-0064953-4" 0603 1259,1550 r90 top locked value=10uF
C63 "CL05B104KO5NNNC" 0402S 1166,1539 r90 top locked value=0.1uF
C64 "CMP-0009655-3" 0201 959.69,994.26 r270 top value=0.1uF
C65 "0402N100J500CT" 0402S 1003,1699.33 r270 top locked value=10pF
C66 "0402N100J500CT" 0402S 1217,1705 r270 top locked value=10pF
C67 "0402N6R2C500CT" 0402S 866.89,837 r180 top locked value=6.2pF
C68 "GJM0335C1ER60BB01D" 0201_033 1257.24,1116.74 r270 top value=0.6pF
C69 "0402N6R2C500CT" 0402S 782.17,905 r270 top locked value=6.2pF
C70 "0402B103K500CT" 0402S 689,2025 r0 top locked value=0.01uF
C71 "0402B103K500CT" 0402S 239,2215 r0 top locked value=0.01uF
C72 "0402B103K500CT" 0402S 689,2225 r180 top locked value=0.01uF
C73 "0402B103K500CT" 0402S 590.2,1915.96 r0 top locked value=0.01uF
C74 "0402B103K500CT" 0402S 359,1915 r180 top locked value=0.01uF
C75 "CL05B104KO5NNNC" 0402S 511.81,114.17 r180 top locked value=0.1uF
C76 "CL05B104KO5NNNC" 0402S 273,-15.38 r0 top locked value=0.1uF
C77 "CL05B104KO5NNNC" 0402S 156,64.62 r180 top locked value=0.1uF
C78 "CL21A106KPFNNNE" 0805#1 1696,3314 r180 top locked value=10uF
C79 "CL21A226KOQNNNE" 0805#1 1696,3415 r180 top locked value=22uF
C80 "CL21A106KPFNNNE" 0805#1 1547,3516 r270 top locked value=10uF
C81 "CMP-0008934-2" 1206_180M 1489,1758 r90 top locked value=100uF
C82 "CMP-0008934-2" 1206_180 1385,1758 r90 top locked value=100uF
D1 "CMP-0002871-1" SML-31_Red 48,2687 r270 top locked value=Red
D2 "CMP-0002834-1" LED_SML-LX0603GW -19,2690 r90 top locked value=Green
D3 "CMP-0002892-2" WL-SMCW_YELLOW 1131,3734.7 r270 top locked value=Yellow
D4 "CDBU00340" SOD-523F 1568.87,1029.64 r270 top value=45V
D5 "CDBU00340" SOD-523F 2043,1263 r180 top locked value=45V
D6 "CMP-0002871-1" SML-31_Red 1864.21,2531.73 r90 top value=Red
D7 "CMP-0003017-2" EAST1616_RGB 1523.34,-4.33 r90 top locked value=Rgb
D8 "CMP-0002871-1" SML-31_Red 1576,3229 r0 top locked value=Red
E1 "CMP-0001857-1" Ethertronics_M830520 965.6,-42.91 r270 top locked
FID1 "CMP-0077181-1" Fiducial10-20 2094.68,141.5 r90 top
FID2 "CMP-0077181-1" Fiducial10-20 2094.68,141.5 r90 bottom
FID3 "CMP-0077181-1" Fiducial10-20 0,145 r90 top
FID4 "CMP-0077181-1" Fiducial10-20 0,145 r90 bottom
FID5 "CMP-0077181-1" Fiducial10-20 1955.31,3858 r90 top
FID6 "CMP-0077181-1" Fiducial10-20 1955.31,3858 r90 bottom locked
FL1 "CMP-0002039-2" TDK_DEA202450BT-1294C1-H 1255.31,789.51 r0 top locked value="1.02 dB"
FL2 "CMP-0002038-2" TDK_DEA165538BT-2236B1-H 1077.81,753.87 r270 top
J1 "CMP-0055832-1" Hustsan_SMA-10V21-TGG 824.87,514.21 r0 top
J2 "U.FL-R-SMT-1(01)" CONN_UFL-R-SMT-1#1 1295.31,440.99 r270 top locked
J3 "U.FL-R-SMT-1(01)" CONN_UFL-R-SMT-1#2 764.84,514.21 r180 top locked
J4 "CMP-0054806-2" WURTH_61301021121 1001,2464 r180 top locked
J5 "CMP-0075101-1" Tag_TC2050-NL#1 15,3461 r180 bottom
J6 "CMP-0055311-1" Molex_1051640001 288,3931.21 r180 top
J7 "CMP-0075533-1" Samtec_FTSH-105-01-x-D-K 1619.19,3018.01 r270 top
J8 "CMP-0075533-1" Samtec_FTSH-105-01-x-D-K 1618.28,2730.77 r270 top
J9 "CMP-0054796-1" WURTH_61300311121 701,2514 r90 top locked
J10 "CMP-0054796-1" WURTH_61300311121 601,2514 r90 top locked
J11 "CMP-0055564-1" Samtec_FTSH-107-01-x-DV 1109,2095.32 r270 top locked
J12 "CMP-0054794-1" WURTH_61300211121 1749,523 r270 top locked
J13 "TC2050-IDC-NL-FP" Tag_TC2050-NL#2 565,1794 r270 top locked
J14 "CMP-0054796-1" WURTH_61300311121 1646.01,2004.79 r0 top locked
J15 "CMP-0054796-1" WURTH_61300311121 1545.12,2325.12 r90 top locked
J16 "CMP-0054796-1" WURTH_61300311121 1645.12,2325.12 r90 top locked
J17 "CMP-0054796-1" WURTH_61300311121 1745.12,2325.12 r90 top locked
J18 "CMP-0054794-1" WURTH_61300211121 0.21,2315.71 r270 top locked
J19 "CMP-0054794-1" WURTH_61300211121 425,401 r90 top locked
J20 "CMP-0054794-1" WURTH_61300211121 525,401 r90 top locked
J21 "CMP-0054794-1" WURTH_61300211121 501,2464 r90 top locked
J22 "CMP-0054794-1" WURTH_61300211121 1301,2464 r270 top locked
J23 "CMP-0054794-1" WURTH_61300211121 301,2464 r90 top locked
J24 "CMP-0054794-1" WURTH_61300211121 401,2464 r90 top locked
J25 "CMP-0054794-1" WURTH_61300211121 1391.23,180.06 r90 top locked
J26 "CMP-0054796-1" WURTH_61300311121 1940,475 r90 top locked
J27 "CMP-0054796-1" WURTH_61300311121 160,450 r90 top locked
J28 "CMP-0054794-1" WURTH_61300211121 201,2464 r90 top locked
L1 "LQG15HZ22NH02D" 0402S 1275.31,721.28 r0 top value=22nH
L2 "LQG15HZ6N8H02D" 0402S 1057.81,634.5 r180 top value=6.8nH
L3 "CMP-0058633-2" 0402S 1079.46,144.21 r180 top value=3.9nH
L4 "LQG15WH2N7C02D" 0402S 1057.81,813.97 r0 top value=2.7nH
L5 "CMP-0003309-1" 0402 150,3713 r180 top locked value="10 ohm"
L6 "CMP-0003309-1" 0402 422,3715 r0 top locked value="10 ohm"
L7 "CMP-0058761-1" LQM2MPN_G0 1426,1172.87 r90 top locked value=2.2uH
L9 "CMP-0058750-1" 1008 1461,1276 r180 top locked value=1uH
L10 "CMP-0058761-1" LQM2MPN_G0 1426.13,1485 r180 top locked value=2.2uH
L11 "CMP-0062710-1" MLP2520S-M 1364,1595 r0 top locked value=10uH
L12 "CMP-0059580-1" 0805#2 1759,3538 r270 top locked value=2.2uH
Label1 "CMP-0003625-1" Label_650x200 1566.9,3812.4 r180 top
Logo1 "WEEE logo" WEEE_Minimum 716.13,763.12 r180 bottom
Logo2 "Texas Instruments" TI_Stacked_Overlay_Small 1027.75,1072.34 r180 bottom
Logo3 "FCC disclaimer" FCC_disclaimer_stacked 898,3575 r180 bottom locked
Logo4 "ESD Susceptible" ESD_Overlay_Medium 2017.5,3355.49 r0 top
Logo5 "CMP-0074844-1" CE_Mark_5mm 1122.69,745.21 r180 bottom
Logo6 "Texas Instruments" TI_Symbol_Overlay_Small 2018.83,3088.35 r0 top
P1 "CRD-081413-A-G" Major_CRD-081413-A-x 1899.91,1199 r180 bottom locked
P2 "CRD-081413-A-G" Major_CRD-081413-A-x 199.91,1199 r180 bottom locked
Q1 "CMP-0000755-1" SOT-23 1307,3591 r90 top locked value=50V
Q2 "CMP-0000014-2" SOT-363 2013.3,2828.2 r0 top locked value=-50V
Q3 "CMP-0000059-2" SSOT-3 1864.21,2669.21 r180 top locked value=-30V
Q4 "CMP-0000755-1" SOT-23 1901.3,197.82 r270 top locked value=50V
Q5 "CMP-0000755-1" SOT-23 1688.9,192.82 r270 top locked value=50V
Q6 "CMP-0000059-2" SSOT-3 1748.9,339.23 r90 top locked value=-30V
Q7 "CMP-0000755-1" SOT-23 1521.49,192.82 r270 top locked value=50V
R1 "CRCW02010000Z0ED" 0201 1148.06,977.77 r90 top value=0
R2 "CMP-0026992-2" 0402S 1235.31,606.65 r0 top locked value=0
R3 "CMP-0026992-2" 0402S 1079.42,514.35 r180 top value=0
R4 "CMP-0026992-2" 0402S 1099.46,494.21 r270 top value=0
R5 "CMP-0026696-1" 0402 952,2716 r180 top locked value=33.0
R6 "CMP-0026992-2" 0402 204,3526 r0 top locked value=0
R7 "CMP-0026696-1" 0402 994,2776 r180 top locked value=33.0
R8 "CMP-0026824-3" 0402 205.21,3477.21 r0 top locked value=100
R9 "CMP-0026696-1" 0402 994,2825 r180 top locked value=33.0
R10 "CMP-0026696-1" 0402 994,2879 r180 top locked value=33.0
R11 "CMP-0026696-1" 0402 994,2928 r180 top locked value=33.0
R12 "CMP-0026696-1" 0402 994,2977 r180 top locked value=33.0
R13 "CMP-0026696-1" 0402 994,3025 r180 top locked value=33.0
R14 "CMP-0026823-3" 0402 1071.33,3496.62 r180 top locked value=100k
R15 "CMP-0026905-2" 0402 129,2802 r270 top locked value=330k
R16 "CMP-0026877-2" 0402 179,2802 r270 top locked value=220k
R17 "CMP-0026825-5" 0402 1071.33,3448.69 r180 top locked value=10k
R18 "CMP-0025756-4" 0603 -18,2840 r270 top locked value=220
R19 "CMP-0025756-4" 0603 50,2840 r270 top locked value=220
R20 "CMP-0025765-4" 0603 1202,3735 r90 top locked value=270
R21 "CMP-0026656-1" 0402 1050.62,3823.02 r180 top locked value=100
R22 "CMP-0026852-3" 0402 999.38,3414 r180 top locked value=1.0k
R23 "CMP-0026852-3" 0402 1005,3363 r180 top locked value=1.0k
R24 "CMP-0026852-3" 0402 1005,3311 r180 top locked value=1.0k
R25 "CMP-0026852-3" 0402 1005,3260 r180 top locked value=1.0k
R26 "CMP-0026825-5" 0402 728,3607 r180 top locked value=10k
R27 "CMP-0025698-4" 0603 546.5,3873.35 r180 top locked value=100k
R28 "CMP-0026852-3" 0402 1272,2866 r90 top locked value=1.0k
R29 "CMP-0025951-3" 0402 728,3660 r180 top locked value=100
R30 "CMP-0022457-4" 0603 1015,3203 r180 top locked value=4.87k
R31 "CMP-0026852-3" 0402 1814.24,2955.63 r180 top locked value=1.0k
R32 "CMP-0026946-3" 0402 813,3482 r270 top locked value=51
R33 "CMP-0026823-3" 0402 1389.6,3413.41 r180 top locked value=100k
R34 "CMP-0026696-1" 0402 1281.6,3413.41 r180 top locked value=33.0
R35 "CMP-0026852-3" 0402 1799.13,2797 r270 top locked value=1.0k
R36 "CMP-0026696-1" 0402 1383.6,3202.41 r180 top locked value=33.0
R37 "CMP-0026852-3" 0402 1159.21,1894.21 r270 top locked value=1.0k
R38 "CMP-0025787-4" 0603 1009,1874 r90 top locked value=33
R39 "CMP-0025787-4" 0603 942,1873 r90 top locked value=33
R40 "CMP-0025874-3" 0603 816,1693 r180 top locked value=0
R41 "CMP-0026823-3" 0402 1314.39,944.25 r180 top locked value=100k
R42 "CMP-0026992-2" 0402 432.3,1002 r180 top locked value=0
R43 "CMP-0026992-2" 0402 543.38,1004 r0 top value=0
R44 "CMP-0026823-3" 0402 419,1099 r0 top locked value=100k
R45 "CMP-0026823-3" 0402 695,1230 r90 top locked value=100k
R46 "CMP-0026823-3" 0402 710.53,1122.38 r270 top locked value=100k
R47 "CMP-0026992-2" 0402 1467,1591 r270 top locked value=0
R48 "CMP-0026992-2" 0402 1274,1674 r90 top locked value=0
R49 "CMP-0026992-2" 0402 942.12,857.4 r90 top locked value=0
R50 "CMP-0026992-2" 0402 48,888 r180 top locked value=0
R51 "CMP-0026886-3" 0402 1545.12,2115.12 r90 top locked value=270
R52 "CMP-0026510-2" 0402 1646.01,2114.79 r90 top locked value=69.8k
R53 "CMP-0026510-2" 0402 1745.12,2114.79 r90 top locked value=69.8k
R54 "CMP-0026992-2" 0402 518.62,947 r180 top locked value=0
R55 "CMP-0026890-5" 0402 1525,1165 r90 top locked value=2.2k
R56 "CMP-0026823-3" 0402 1460.5,2401.5 r270 top locked value=100k
R57 "CMP-0026510-2" 0402 1415,2401.38 r270 top locked value=69.8k
R58 "CMP-0026510-2" 0402 1830.63,2401.17 r270 top locked value=69.8k
R59 "CMP-0026825-5" 0402 1578,1165 r270 top locked value=10k
R60 "CMP-0026992-2" 0402 1738.85,1621.94 r0 top value=0
R61 "CMP-0026992-2" 0402 1740.62,1514.63 r0 top value=0
R62 "CMP-0026823-3" 0402 1665.41,1892.69 r0 top locked value=100k
R63 "CMP-0026823-3" 0402 1817.16,1824.58 r0 top value=100k
R64 "CMP-0025874-3" 0603 321,1812 r270 top locked value=0
R65 "CMP-0026992-2" 0402 2055,1550 r0 top locked value=0
R66 "CMP-0025874-3" 0603 257,1812 r270 top locked value=0
R67 "CMP-0026992-2" 0402 1739.21,1659.21 r0 top locked value=0
R68 "CMP-0026992-2" 0402 1740,1550 r0 top locked value=0
R69 "CMP-0026992-2" 0402 2055,1598 r0 top locked value=0
R70 "CMP-0026992-2" 0402 1740,1450 r0 top locked value=0
R71 "CMP-0026992-2" 0402 2056.08,1450 r0 top locked value=0
R72 "CMP-0026992-2" 0402 1740,1350 r0 top locked value=0
R73 "CMP-0026992-2" 0402 2055,1369 r0 top locked value=0
R74 "CMP-0026992-2" 0402 48,1549 r0 top locked value=0
R75 "CMP-0026992-2" 0402 1740,1250 r0 top locked value=0
R76 "CMP-0026992-2" 0402 48,1441 r0 top locked value=0
R77 "CMP-0026992-2" 0402 342,1449 r0 top locked value=0
R78 "CMP-0026992-2" 0402 1740,1150 r0 top locked value=0
R79 "CMP-0026992-2" 0402 2060,1150 r0 top locked value=0
R80 "CMP-0026992-2" 0402 48,1356 r0 top locked value=0
R81 "CMP-0026992-2" 0402 343,1349 r0 top locked value=0
R82 "CMP-0026992-2" 0402 1740,1050 r0 top locked value=0
R83 "CMP-0026992-2" 0402 2060,1050 r0 top locked value=0
R84 "CMP-0026992-2" 0402 48,1249 r0 top locked value=0
R85 "CMP-0026992-2" 0402 337.11,1249.01 r0 top locked value=0
R86 "CMP-0026992-2" 0402 1740,950 r0 top locked value=0
R87 "CMP-0026992-2" 0402 2060,950 r0 top locked value=0
R88 "CMP-0026992-2" 0402 48,1150 r0 top locked value=0
R89 "CMP-0026992-2" 0402 335.71,1149.11 r0 top locked value=0
R90 "CMP-0026992-2" 0402 1740,850 r0 top locked value=0
R91 "CMP-0026992-2" 0402 2055,850 r0 top locked value=0
R92 "CMP-0026992-2" 0402 48.15,1069.21 r0 top locked value=0
R93 "CMP-0026992-2" 0402 338,1049 r0 top locked value=0
R94 "CMP-0026992-2" 0402 1740,750 r0 top locked value=0
R95 "CMP-0026992-2" 0402 2053,748.99 r0 top locked value=0
R96 "CMP-0026992-2" 0402 48,975 r0 top locked value=0
R97 "CMP-0026992-2" 0402 337,949 r0 top locked value=0
R98 "CMP-0026992-2" 0402 48,843 r0 top locked value=0
R99 "CMP-0026992-2" 0402 339,849 r0 top locked value=0
R100 "CMP-0026992-2" 0402 48,750 r0 top locked value=0
R101 "CMP-0026992-2" 0402 340,704 r0 top locked value=0
R102 "CMP-0026992-2" 0402 1740,1400 r0 top locked value=0
R103 "CMP-0026992-2" 0402 1740,1301 r0 top locked value=0
R104 "CMP-0026992-2" 0402 2060,1204 r0 top locked value=0
R105 "CMP-0026992-2" 0402 2060,1100 r0 top locked value=0
R106 "CMP-0026992-2" 0402 340,749 r0 top locked value=0
R107 "CMP-0026992-2" 0402 1740,1201 r0 top locked value=0
R108 "CMP-0026992-2" 0402 48,800 r0 top locked value=0
R109 "CMP-0026992-2" 0402 70.4,665.51 r90 top locked value=0
R110 "CMP-0026992-2" 0402 452.38,735 r0 top locked value=0
R111 "CMP-0026992-2" 0402 24.21,665.51 r90 top locked value=0
R112 "CMP-0026992-2" 0402 776,2154 r270 top locked value=0
R113 "CMP-0026992-2" 0402 143,2187 r270 top locked value=0
R114 "CMP-0026699-1" 0402 239,2165 r180 top locked value=470
R115 "CMP-0026455-2" 0402 239,2115 r0 top locked value=576k
R116 "CMP-0026699-1" 0402 689,2175 r0 top locked value=470
R117 "CMP-0026455-2" 0402 689,2125 r180 top locked value=576k
R118 "CMP-0026373-2" 0402 239,2065 r0 top locked value=422k
R119 "CMP-0026373-2" 0402 689,2075 r180 top locked value=422k
R120 "CMP-0026992-2" 0402 473,1927 r270 top locked value=0
R121 "CMP-0026992-2" 0402 239,1909 r180 top locked value=0
R122 "CMP-0026699-1" 0402 590.2,1965.96 r180 top locked value=470
R123 "CMP-0026992-2" 0402 519.21,1927 r270 top locked value=0
R124 "CMP-0026699-1" 0402 359,1965 r0 top locked value=470
R125 "CMP-0026992-2" 0402 429.64,1941.38 r270 top locked value=0
R126 "CMP-0026455-2" 0402 689,1975 r180 top locked value=576k
R127 "CMP-0026455-2" 0402 239,2015 r0 top locked value=576k
R128 "CMP-0026373-2" 0402 689,1925 r180 top locked value=422k
R129 "CMP-0026373-2" 0402 239,1965 r0 top locked value=422k
R130 "CMP-0026992-2" 0402 511.81,149.61 r180 top locked value=0
R131 "CMP-0026992-2" 0402 351,-12.38 r270 top locked value=0
R132 "CMP-0026992-2" 0402 402.38,641.52 r0 top locked value=0
R133 "CMP-0026918-5" 0402 97.48,234 r0 top locked value=3.3k
R134 "CMP-0026918-5" 0402 321,195.62 r90 top value=3.3k
R135 "CMP-0026992-2" 0402 402.38,591.52 r0 top locked value=0
R136 "CMP-0026992-2" 0402 452.38,689.21 r0 top locked value=0
R137 "CMP-0026992-2" 0402 171,146.62 r270 top locked value=0
R138 "CMP-0026992-2" 0402 518.92,196.35 r180 top locked value=0
R139 "CMP-0026992-2" 0402 548.62,592.52 r180 top locked value=0
R140 "CMP-0026992-2" 0402 221,194.62 r270 top locked value=0
R141 "CMP-0020616-2" 0805_HV 629.63,251.68 r90 top locked value=0
R142 "CMP-0026992-2" 0402 548.62,642.52 r180 top locked value=0
R143 "CMP-0026992-2" 0402 549.21,529.21 r180 top locked value=0
R144 "CMP-0026992-2" 0402 542.54,219.98 r270 top locked value=0
R145 "CMP-0026992-2" 0402 122,155.62 r270 top locked value=0
R146 "CMP-0026992-2" 0402 351,91.62 r270 top locked value=0
R147 "CMP-0026992-2" 0402 271,194.62 r270 top locked value=0
R148 "CMP-0026992-2" 0402 433.07,78.74 r0 top locked value=0
R149 "CMP-0026992-2" 0402 433.07,39.37 r0 top value=0
R150 "CMP-0026852-3" 0402 3,1719 r180 top locked value=1.0k
R151 "CMP-0026852-3" 0402 2088.64,2129.21 r180 top locked value=1.0k
R152 "CMP-0026823-3" 0402 2060,1318 r180 top locked value=100k
R153 "CMP-0026659-1" 0402 1895.3,2796.2 r180 top locked value=100k
R154 "CMP-0026825-5" 0402 2027.08,2729.21 r180 top locked value=10k
R155 "CMP-0026825-5" 0402 1895.3,2856.2 r180 top locked value=10k
R156 "CMP-0026825-5" 0402 -13,2150 r0 top locked value=10k
R157 "CMP-0026825-5" 0402 2088.64,1739.21 r0 top locked value=10k
R158 "CMP-0025765-4" 0603 1924.21,2530.75 r270 top value=270
R159 "CMP-0026852-3" 0402 1960.07,2149.21 r90 top locked value=1.0k
R160 "CMP-0025765-4" 0603 1700.5,3229 r180 top locked value=270
R161 "CMP-0026823-3" 0402 1837,3537 r270 top locked value=100k
R162 "CMP-0025939-3" 0603 1630,55.71 r270 top locked value=750
R163 "CMP-0025939-3" 0603 1695,40 r270 top locked value=750
R164 "CMP-0025939-3" 0603 1525,85 r0 top locked value=750
R165 "CMP-0026992-2" 0402 1505.43,334.21 r0 top locked value=0
R166 "CMP-0025874-3" 0603 1643.9,344.23 r90 top locked value=0
R167 "CMP-0026992-2" 0402 1505.43,379.21 r0 top locked value=0
R168 "CMP-0026992-2" 0402 1505.43,419.21 r0 top locked value=0
R169 "CMP-0026823-3" 0402 1886.62,79.21 r180 top locked value=100k
R170 "CMP-0026823-3" 0402 1791.47,79.21 r0 top locked value=100k
R171 "CMP-0026823-3" 0402 1505.43,469.21 r0 top locked value=100k
R172 "CMP-0026992-2" 0402 1792.2,221.07 r90 top locked value=0
SH-J3 "CMP-0003761-1" Wurth_60900213421 432.14,403.65 r90 top
SH-J4 "CMP-0003761-1" Wurth_60900213421 533.23,404.53 r90 top
SH-J5 "CMP-0003761-1" Wurth_60900213421 1395.79,178.84 r90 top
SH-J6 "CMP-0003761-1" Wurth_60900213421 1750.18,523.3 r90 top
SH-J7 "CMP-0003761-1" Wurth_60900213421 1296.35,2465.8 r90 top
SH-J8 "CMP-0003761-1" Wurth_60900213421 1550.24,2371.71 r90 top
SH-J9 "CMP-0003761-1" Wurth_60900213421 1750.51,2371.77 r90 top
SH-J10 "CMP-0003761-1" Wurth_60900213421 1699.42,2005.11 r180 top
SH-J11 "CMP-0003761-1" Wurth_60900213421 1650.51,2271.77 r90 top
SH-J12 "CMP-0003761-1" Wurth_60900213421 1203.06,2463.14 r90 top
SH-J13 "CMP-0003761-1" Wurth_60900213421 903.06,2463.14 r90 top
SH-J14 "CMP-0003761-1" Wurth_60900213421 1003.06,2463.14 r90 top
SH-J15 "CMP-0003761-1" Wurth_60900213421 710.83,2552.6 r90 top
SH-J16 "CMP-0003761-1" Wurth_60900213421 803.06,2463.14 r90 top
SH-J17 "CMP-0003761-1" Wurth_60900213421 206.38,2462.7 r90 top
SH-J18 "CMP-0003761-1" Wurth_60900213421 1096.89,2465.5 r90 top
SH-J19 "CMP-0003761-1" Wurth_60900213421 -4.41,2322.16 r90 top
SH-J20 "CMP-0003761-1" Wurth_60900213421 400.93,2463.2 r90 top
SH-J21 "CMP-0003761-1" Wurth_60900213421 504.81,2462.37 r90 top
SH-J22 "CMP-0003761-1" Wurth_60900213421 602.51,2553 r90 top
SH-J23 "CMP-0003761-1" Wurth_60900213421 304.83,2463.02 r90 top
SW1 "CMP-0002328-1" SW_1188E 797.38,3850.58 r270 top locked
SW2 "CMP-0002328-1" SW_1188E 7.42,1934.59 r0 top locked
SW3 "CMP-0002328-1" SW_1188E 2092.58,1934.59 r180 top locked
SW4 "B3U-3000P" SW_B3U-3000P 2142.4,2325.03 r180 top
TP1 "CMP-0078143-2" TESTPOINT 1254.21,1894.21 r270 top locked
TP2 "5015" Testpoint_Keystone_Miniature 2078.57,3558.33 r90 top locked
U1 "CMP-0002040-1" TDK_DPX165950DT-8148A1 1099.46,588.93 r270 top
U2 "RTC6608OSP" Richwave_RTC6608OSP 1077.81,932.62 r270 top
U3 "CMP-0029864-2" PDT0128A 599,3085 r90 top locked
U4 "CMP-0051039-3" DCK0006A_N#1 1092,3566 r0 top locked
U5 "CMP-0043121-2" DQA0010A 261.87,3592.11 r270 top locked
U6 "CMP-0033095-1" DBZ0003A_N 1181,2792 r270 top locked
U7 "CMP-0051039-3" DCK0006A_N#2 1347.6,3320.41 r180 top locked
U8 "CMP-0051039-3" DCK0006A_N#1 1334.71,3123.41 r180 top locked
U9 "CMP-0004903-1" SOP-8_150MIL 570,1208.22 r90 top locked
U10 "CC3235SF12RGKR" RGK0064B 1020,1260 r0 top locked
U11 "CMP-0041122-1" PW0014A_N 459,2102 r180 top locked
U12 "TMP116AIDRVR" DRV0006A 535.13,48.96 r90 top
U13 "BMA280" 12LGA 256,79.62 r0 top locked
U14 "CMP-0037789-2" DSG0008A 1660,3538 r0 top
Y1 "CMP-0004648-3" XTAL_ABM3 495,3566 r0 top locked
Y2 "CMP-0004575-3" XTAL_ABS07 1108,1685 r180 top locked
Y3 "8Y40072002" TXC_8Y 868.86,921.14 r0 top locked
ZZ1 "This Assembly Note is for PCB labels only" AssemblyNoteLabel -963.19,4611.57 r0 top locked
ZZ2 "These assemblies are ESD sensitive, ESD precautions shall be observed." AssemblyNote -956.19,4482.57 r0 top locked
ZZ3 "These assemblies must be clean and free from flux and all contaminants. Use of no clean flux is not acceptable." AssemblyNote -955.19,4343.57 r0 top locked
ZZ4 "These assemblies must comply with workmanship standards IPC-A-610 Class 2, unless otherwise specified." AssemblyNote -957.19,4206.57 r0 top locked

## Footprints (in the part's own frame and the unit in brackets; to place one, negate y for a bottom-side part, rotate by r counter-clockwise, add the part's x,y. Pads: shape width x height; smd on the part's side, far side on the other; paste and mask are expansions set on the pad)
12LGA [mm] "LGA, 12-Leads, Body 2x2mm, Pitch 0.5mm"
  rect 0.41x0.28 smd: 1(-0.815,0.75) 2(-0.815,0.25) 3(-0.815,-0.25) 4(-0.815,-0.75) 7(0.815,-0.75) 8(0.815,-0.25) 9(0.815,0.25) 10(0.815,0.75)
  rect 0.28x0.41 smd: 5(-0.25,-0.815) 6(0.25,-0.815) 11(0.25,0.815) 12(-0.25,0.815)
  silkscreen extent -1.3,0.7 -0.8,1.2, body extent -1,-1 1,1, height 1.01
0201 [mm] "Data from Kemet datasheet CC101_COM dated 7/28/11"
  rect 0.46x0.42 smd mask+0.048: 1(-0.33,0) 2(0.33,0)
  body extent -0.31,-0.16 0.31,0.16, height 0.26
0201_033 [mm] "SMD, 2-Leads, Height 0.33mm"
  rect 0.46x0.42 smd mask+0.048: 1(-0.33,0) 2(0.33,0)
  body extent -0.31,-0.16 0.31,0.16, height 0.33
0402 [mm] "0402 from SM-752 data"
  rect 0.8x0.6 smd: 1(-0.6,0) 2(0.6,0)
  silkscreen extent -1.22,-0.52 1.22,0.52, body extent -0.55,-0.3 0.55,0.3, height 0.6
0402S [mil] "Based on C0402S footprint from PADS legacy"
  rect 15x24 smd: 1(-20,0) 2(20,0)
  body extent -22,-12 22,12, height 24
0603 [mm] "0603 from SM-752 data"
  rect 1x0.95 smd: 1(-0.8,0) 2(0.8,0)
  silkscreen extent -1.52,-0.69 1.52,0.69, body extent -0.87,-0.47 0.87,0.47, height 1
0805#1 [mm] "0805 from SM-752 data"
  rect 1.3x1.5 smd: 1(-0.85,0) 2(0.85,0)
  silkscreen extent -1.72,-0.97 1.72,0.97, body extent -1.1,-0.72 1.1,0.72, height 1.45
0805#2 [mm] "0805 from SM-752 data"
  rect 1.15x1.45 smd: 1(-0.9,0) 2(0.9,0)
  body extent -1.1,-0.72 1.1,0.72, height 1.45
0805_HV [mil] "0805 with 30mil clearance between pads"
  rect 50x63 smd: 1(-40,0) 2(40,0)
  silkscreen extent -74,-40 74,40, body extent -43,-29 43,29, height 57
1008 [mm] "SMD, Body 2.5x2mm, Height 1.2mm"
  rect 0.8x2.2 smd: 1(-1,0) 2(1,0)
  silkscreen extent -0.4,-1.2 0.4,1.2, body extent -1.35,-1.1 1.35,1.1, height 1.2
1206_180 [mm] "1206_180"
  rect 1.3x1.85 smd: 1(-1.45,0) 2(1.45,0)
  silkscreen extent -0.9,-1.09 0.9,1.09, body extent -1.75,-0.95 1.75,0.95, height 1.8
1206_180M [mm] "1206_180"
  rect 1.3x1.85 smd: 1(-1.45,0) 2(1.45,0)
  silkscreen extent -2.76,-1.44 2.76,1.44, body extent -1.75,-0.95 1.75,0.95, height 1.8
AssemblyNote [mil] "Assembly Note"
AssemblyNoteLabel [mil] "Assembly Note for PCB Labels"
CE_Mark_5mm [mil] "Minimum text height for CE Mark"
  silkscreen extent -138,-98 138,98
CONN_UFL-R-SMT-1#1 [mm] "Hirose recommended land pattern http://www.hirose.co.jp/cataloge_hp/e32119372.pdf 2009.2"
  rect 1.05x1 smd paste-0.1 mask-0.1: 1(-1.525,0)
  rect 2x0.9 on Top Paste: 2(0,1.5) 3(0,-1.5)
  rect 2x0.9 on Top Solder: 2(0,1.5) 3(0,-1.5)
  rect 2.2x1.05 smd paste-2 mask-2: 2(0,1.475) 3(0,-1.475)
  TOP keep-out region: -0.8,-0.7 1.1,-0.7 1.1,0.7 -0.8,0.7
  silkscreen extent -1.7,-1.7 1.7,1.7, body extent -1.55,-1.5 1.55,1.5, height 1.27
CONN_UFL-R-SMT-1#2 [mm] "Hirose recommended land pattern http://www.hirose.co.jp/cataloge_hp/e32119372.pdf 2009.2"
  rect 1.05x1 smd paste-0.1 mask-0.1: 1(-1.525,0)
  rect 2x0.748 on Top Paste: 2(0,1.5) 3(0,-1.5)
  rect 2x0.748 on Top Solder: 2(0,1.5) 3(0,-1.5)
  rect 2.2x1.05 smd paste-2 mask-2: 2(0,1.475) 3(0,-1.475)
  TOP keep-out region: -0.8,-0.7 1.1,-0.7 1.1,0.7 -0.8,0.7
  silkscreen extent -1.7,-1.7 1.7,1.7, body extent -1.55,-1.5 1.55,1.5, height 1.27
DBZ0003A_N [mm] "SOT23, 3-Leads, Body 2.9x1.3mm, Pitch 0.95mm, Lead Span 2.4mm, IPC Medium Density"
  rrect17% 1x0.6 smd: 1(-1.2,0.95) 2(-1.2,-0.95) 3(1.2,0)
  silkscreen extent 0.2,-1.5 0.7,1.5, body extent -1.26,-1.46 1.26,1.46, height 0.98
DCK0006A_N#1 [mm] "SOT23, 6-Leads, Body 2x1.3mm, Pitch 0.65mm, Lead Span 2.1mm, IPC Medium Density"
  rrect25% 0.85x0.4 smd: 1(-1.125,0.65) 2(-1.125,0) 3(-1.125,-0.65) 4(1.125,-0.65) 5(1.125,0) 6(1.125,0.65)
  silkscreen extent -1.5,-1.09 0.51,1.09, body extent -1.14,-1 1.14,1, height 0.95
DCK0006A_N#2 [mm] "SOT23, 6-Leads, Body 2x1.3mm, Pitch 0.65mm, Lead Span 2.1mm, IPC Medium Density"
  rect 0.85x0.4 smd: 1(-0.95,0.65) 2(-0.95,0) 3(-0.95,-0.65) 4(0.95,-0.65) 5(0.95,0) 6(0.95,0.65)
  silkscreen extent -0.51,-1.09 0.51,1.09, body extent -1.14,-1 1.14,1, height 0.95
DQA0010A [mm] "SON, 10-Leads, Body 1x2.5mm, Pitch 0.5mm, TI Recommended"
  rrect50% 0.565x0.2 smd: 1(-0.417,1) 2(-0.417,0.5) 4(-0.417,-0.5) 5(-0.417,-1) 6(0.417,-1) 7(0.417,-0.5) 9(0.417,0.5) 10(0.417,1)
  rrect28% 0.565x0.36 on Top Paste: 3(-0.417,0) 8(0.417,0)
  rrect25% 0.565x0.4 smd paste-0.2: 3(-0.417,0) 8(0.417,0)
  silkscreen extent -0.67,-1.45 0.55,1.45, body extent -0.55,-1.3 0.55,1.3, height 0.56
DRV0006A [mm] "SON, 6-Leads, Body 2x2mm, Pitch 0.65mm, Thermal Pad 1.6x1mm, TI Recommended"
  rrect33% 0.45x0.3 smd: 1(-0.975,0.65) 2(-0.975,0) 3(-0.975,-0.65) 4(0.975,-0.65) 5(0.975,0) 6(0.975,0.65)
  rrect14% 1x0.7 on Top Paste: 7(0,0.45) 7(0,-0.45)
  rrect10% 1x1.6 smd paste-0.5: 7(0,0)
  silkscreen extent -1.05,-1.2 1.05,1.2, body extent -1.05,-1.05 1.05,1.05, height 0.81
DSG0008A [mm] "SON, 8-Leads, Body 2x2mm, Pitch 0.5mm, Thermal Pad 1.6x0.9mm, TI Recommended"
  rrect40% 0.5x0.25 smd: 1(-0.95,0.75) 2(-0.95,0.25) 3(-0.95,-0.25) 4(-0.95,-0.75) 5(0.95,-0.75) 6(0.95,-0.25) 7(0.95,0.25) 8(0.95,0.75)
  rrect14% 0.9x0.7 on Top Paste: 9(0,-0.45) 9(0,0.45)
  rrect11% 0.9x1.6 smd paste-0.45: 9(0,0)
  silkscreen extent -1.07,-1.15 1.07,1.15, body extent -1,-1 1,1, height 0.77
EAST1616_RGB [mm] "SMD, 6-Leads, Body 1.6x1.6mm"
  rect 0.4x0.55 smd: 1(-0.725,0.675) 2(-0.725,-0.675) 5(0.725,0.675) 6(0.725,-0.675)
  rect 0.5x0.7 smd: 3(0,0.75) 4(0,-0.75)
  silkscreen extent -0.9,-1.2 0.9,0.1, body extent -0.8,-0.8 0.8,0.8, height 0.5
ESD_Overlay_Medium [mil]
  silkscreen extent -127,-109 125,110
Ethertronics_M830520 [mm] "SMD, 6-Leads, Body 8x3mm"
  rect 0.9x1.1 smd: 1(-1,3.4) 2(-1,0) 3(-1,-3.4) 4(1,-3.4) 5(1,0) 6(1,3.4)
  silkscreen extent -1.8,-2.4 1.5,2.4, body extent -1.5,-4 1.5,4, height 1.33
FCC_disclaimer_stacked [mil]
Fiducial10-20 [mm]
  round 1 smd mask+0.5: 1(0,0)
  TOP keep-out circle w1.178: c0,0 r0.5
Hustsan_SMA-10V21-TGG [mm] "SMD, 4-Leads, Body 7.1x7.1mm"
  round 1.4 smd: 1(0,0)
  rect 1.8x1.8 smd paste-0.076 mask-0.076: 2(-2.8,2.8) 3(-2.8,-2.8)
  rect 1.8x1.8 smd: 4(2.8,-2.8) 5(2.8,2.8)
  silkscreen extent -3.55,-3.55 3.3,3.55, body extent -3.55,-3.55 3.55,3.55, height 10.72
Label_650x200 [mil] "Thermal Transfer Label"
  round 1 on Mech13: 0(0,0)
  silkscreen extent -325,-100 325,100, body extent -325,-100 325,100, height 1
LED_SML-LX0603GW [mm] "LUMEX OPTO"
  rect 0.8x0.8 smd: 1(-0.75,0) 2(0.75,0)
  silkscreen extent 1.4,-0.4 1.8,0.4, body extent -0.8,-0.4 0.8,0.4, height 0.6
LQM2MPN_G0 [mm] "MuRata"
  rrect12% 0.8x1.8 smd: 1(-0.8,0) 2(0.8,0)
  silkscreen extent -0.2,-1 0.2,1, body extent -1.07,-0.87 1.07,0.87, height 1
Major_CRD-081413-A-x [mm] "Receptacle, 2.54 mm, 10x2, TH"
  rect 1.7x1.7 hole 1.2: 1(1.27,11.43)
  round 1.7 hole 1.2: 2(-1.27,11.43) 3(1.27,8.89) 4(-1.27,8.89) 5(1.27,6.35) 6(-1.27,6.35) 7(1.27,3.81) 8(-1.27,3.81) 9(1.27,1.27) 10(-1.27,1.27) 11(1.27,-1.27) 12(-1.27,-1.27) 13(1.27,-3.81) 14(-1.27,-3.81) 15(1.27,-6.35) 16(-1.27,-6.35) 17(1.27,-8.89) 18(-1.27,-8.89) 19(1.27,-11.43) 20(-1.27,-11.43)
  silkscreen extent -2.52,-12.71 3,12.71, body extent -2.52,-12.71 2.52,12.71, height 8.64
MLP2520S-M [mm] "TDK"
  rect 0.7x2 smd: 1(-1.05,0) 2(1.05,0)
  silkscreen extent -0.5,-1.15 0.5,1.15, body extent -1.32,-1.07 1.32,1.07, height 1
Molex_1051640001 [mm] "Receptacle, USB 2.0, Micro B, 5 Pos, 0.65mm Pitch, R/A, SMT"
  rrect22% 0.45x1.38 smd mask+0: 1(1.3,4.11) 2(0.65,4.11) 3(0,4.11) 4(-0.65,4.11) 5(-1.3,4.11)
  rrect7% 1.475x2.1 smd mask+0: 6(-2.462,3.75) 11(2.462,3.75)
  rrect100% 1.4x2.1 hole 0.6 slot 1.3 at 90 deg: 7(-3.95,1.45) 10(3.95,1.45)
  rrect7% 1.375x1.9 smd: 8(-0.937,1.45) 9(0.937,1.45)
  silkscreen extent 1.2,5.1 1.4,5.4, body extent -4.1,-0.7 4.1,4.47, height 2.45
